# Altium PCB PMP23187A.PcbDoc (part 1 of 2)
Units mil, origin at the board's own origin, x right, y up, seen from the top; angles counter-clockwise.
Board outline 4000 x 3500 mil, 6 copper layers (Top Layer, Signal Layer 1, Signal Layer 2, Signal Layer 3, Signal Layer 4, Bottom Layer), stack 61.8 mil thick; 121 components, 42 nets, 273 pads, 535 vias.
Unrouted connection lines stored in the file: 23.
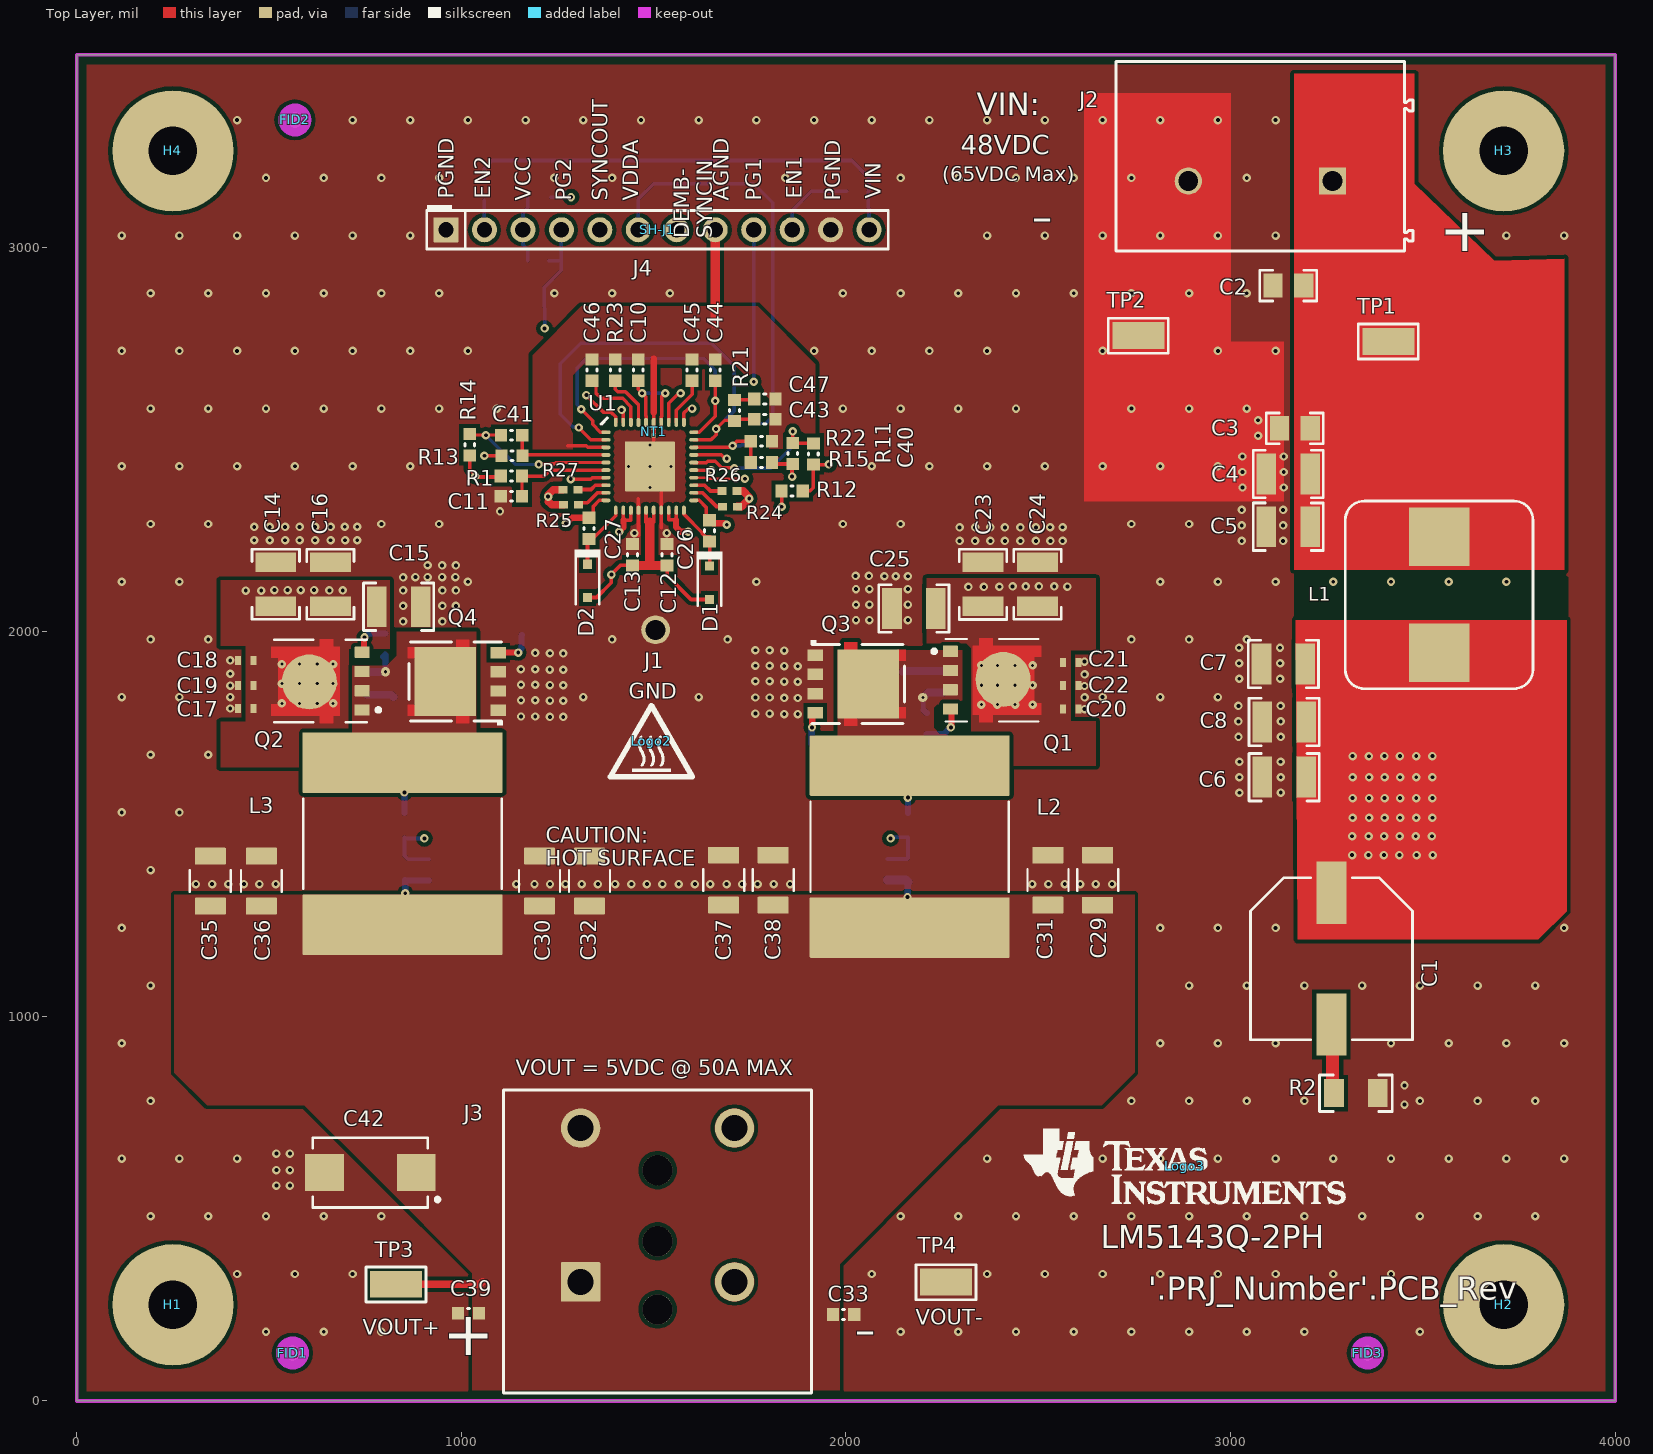
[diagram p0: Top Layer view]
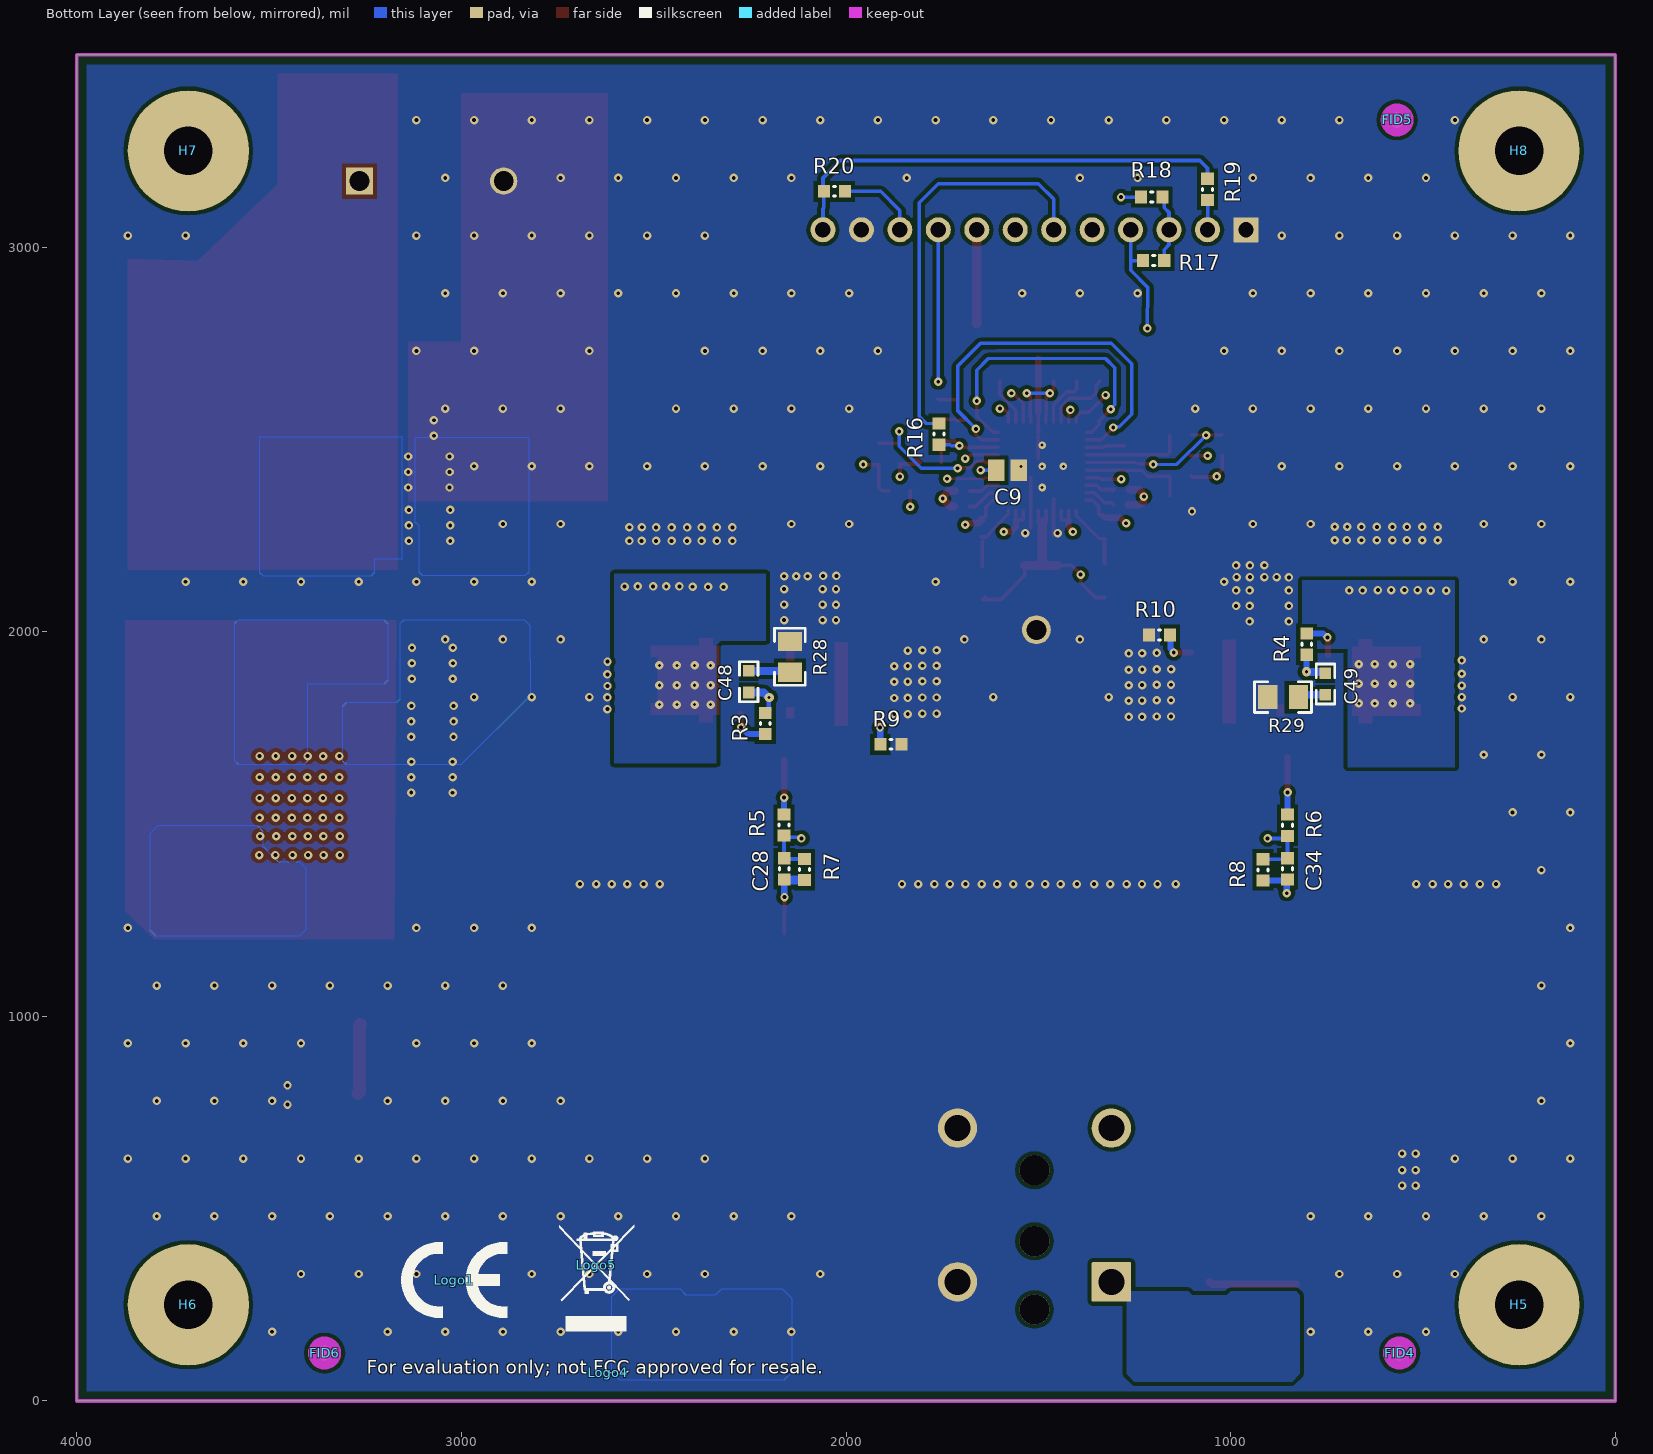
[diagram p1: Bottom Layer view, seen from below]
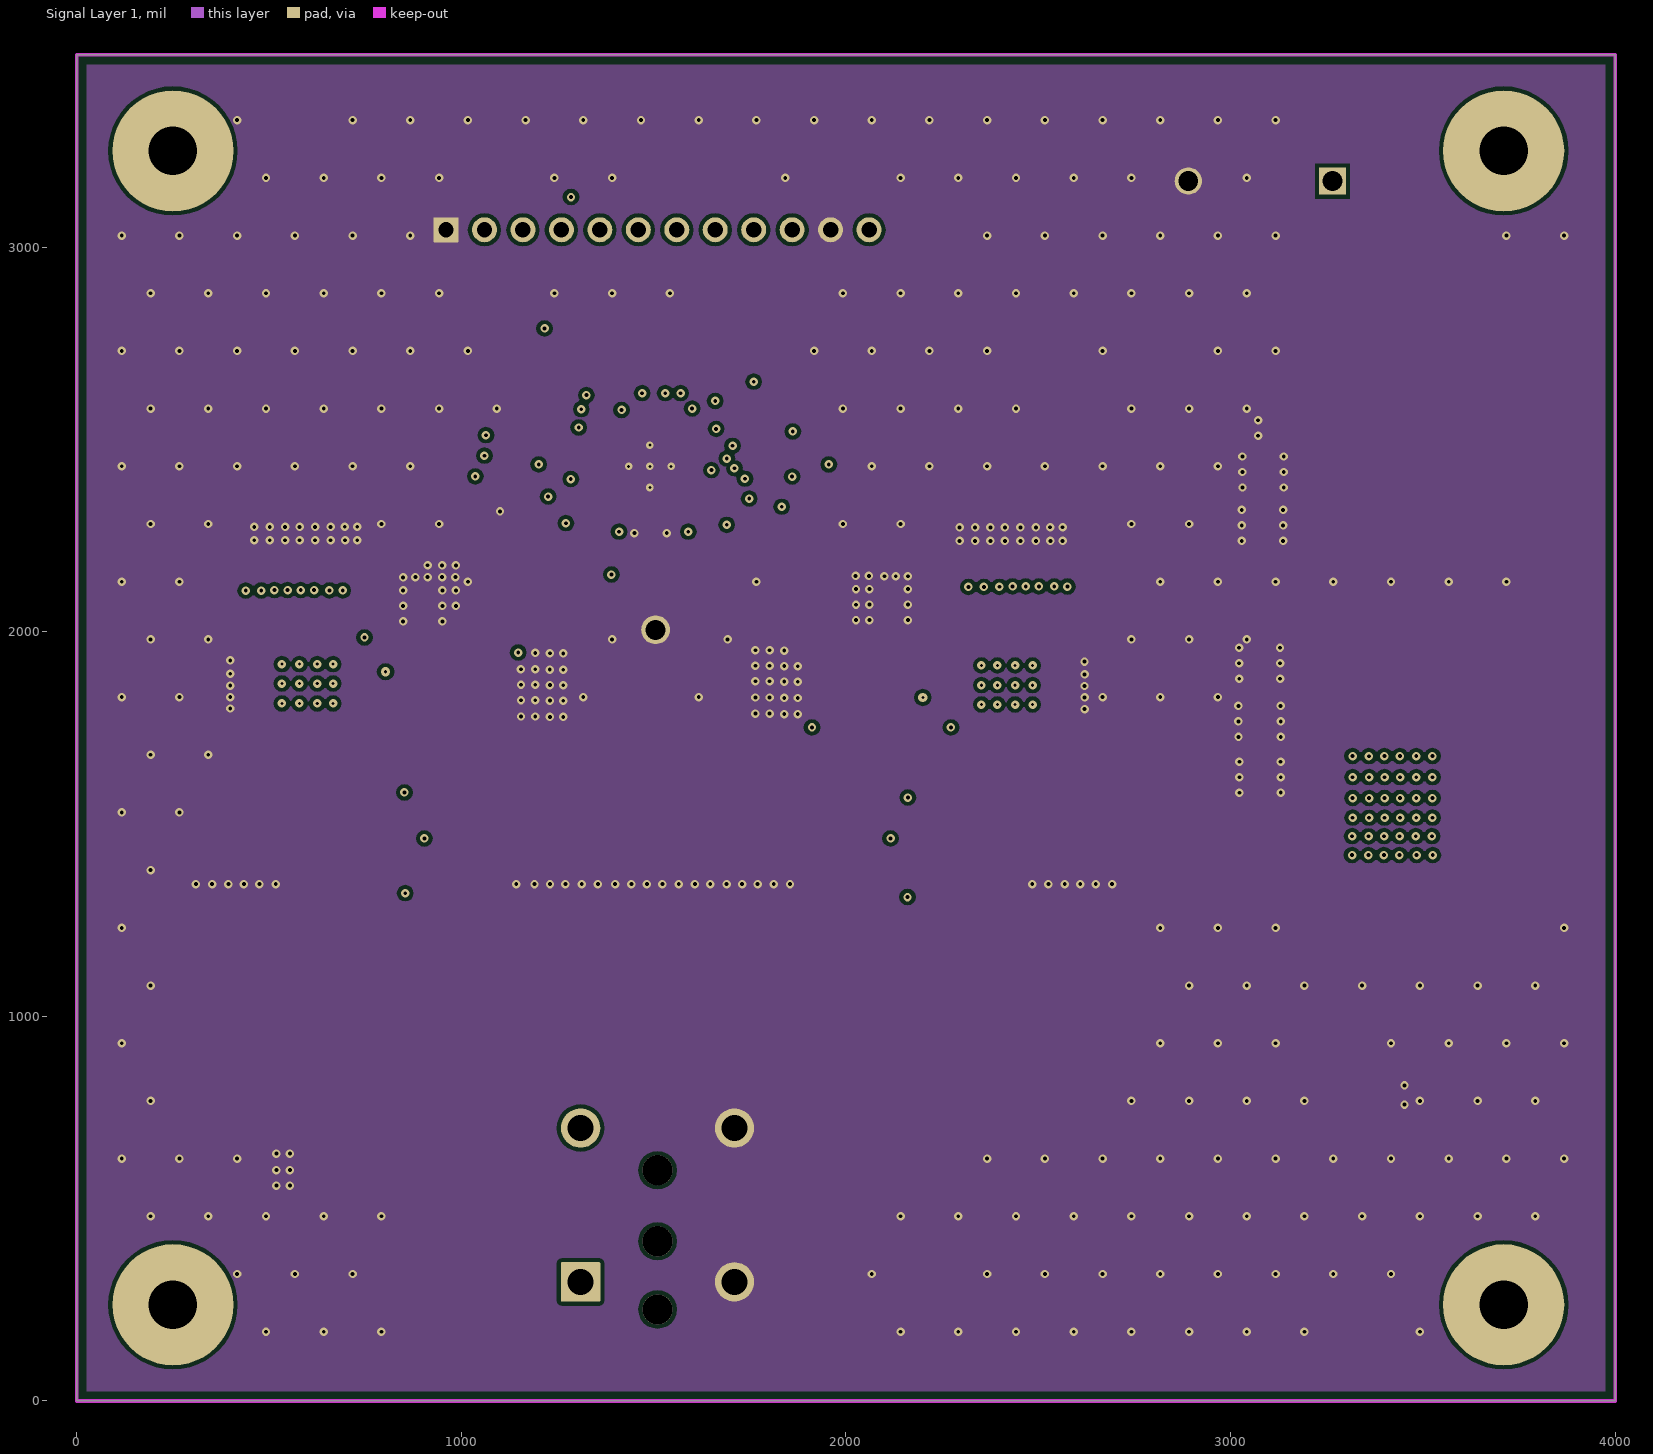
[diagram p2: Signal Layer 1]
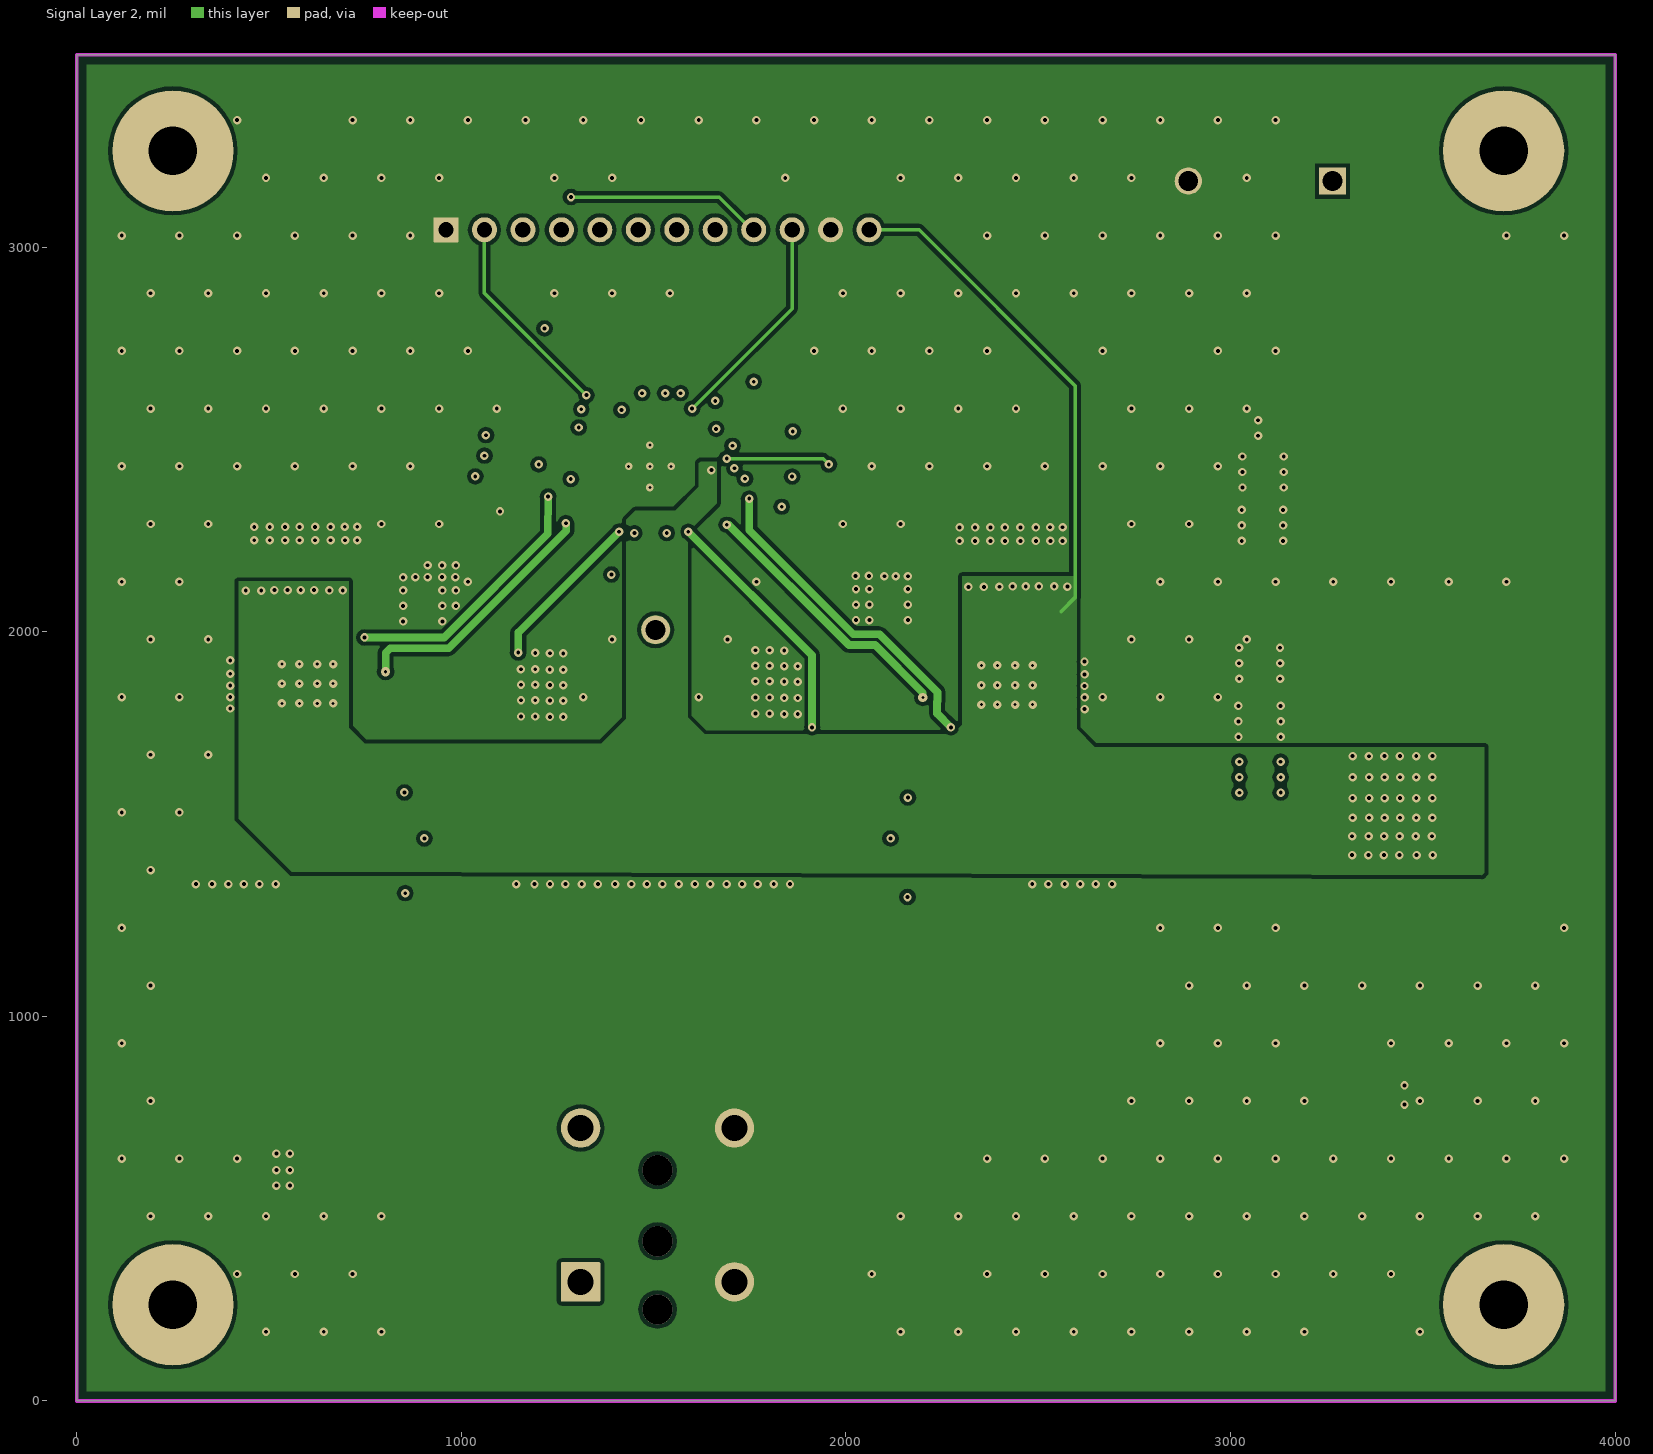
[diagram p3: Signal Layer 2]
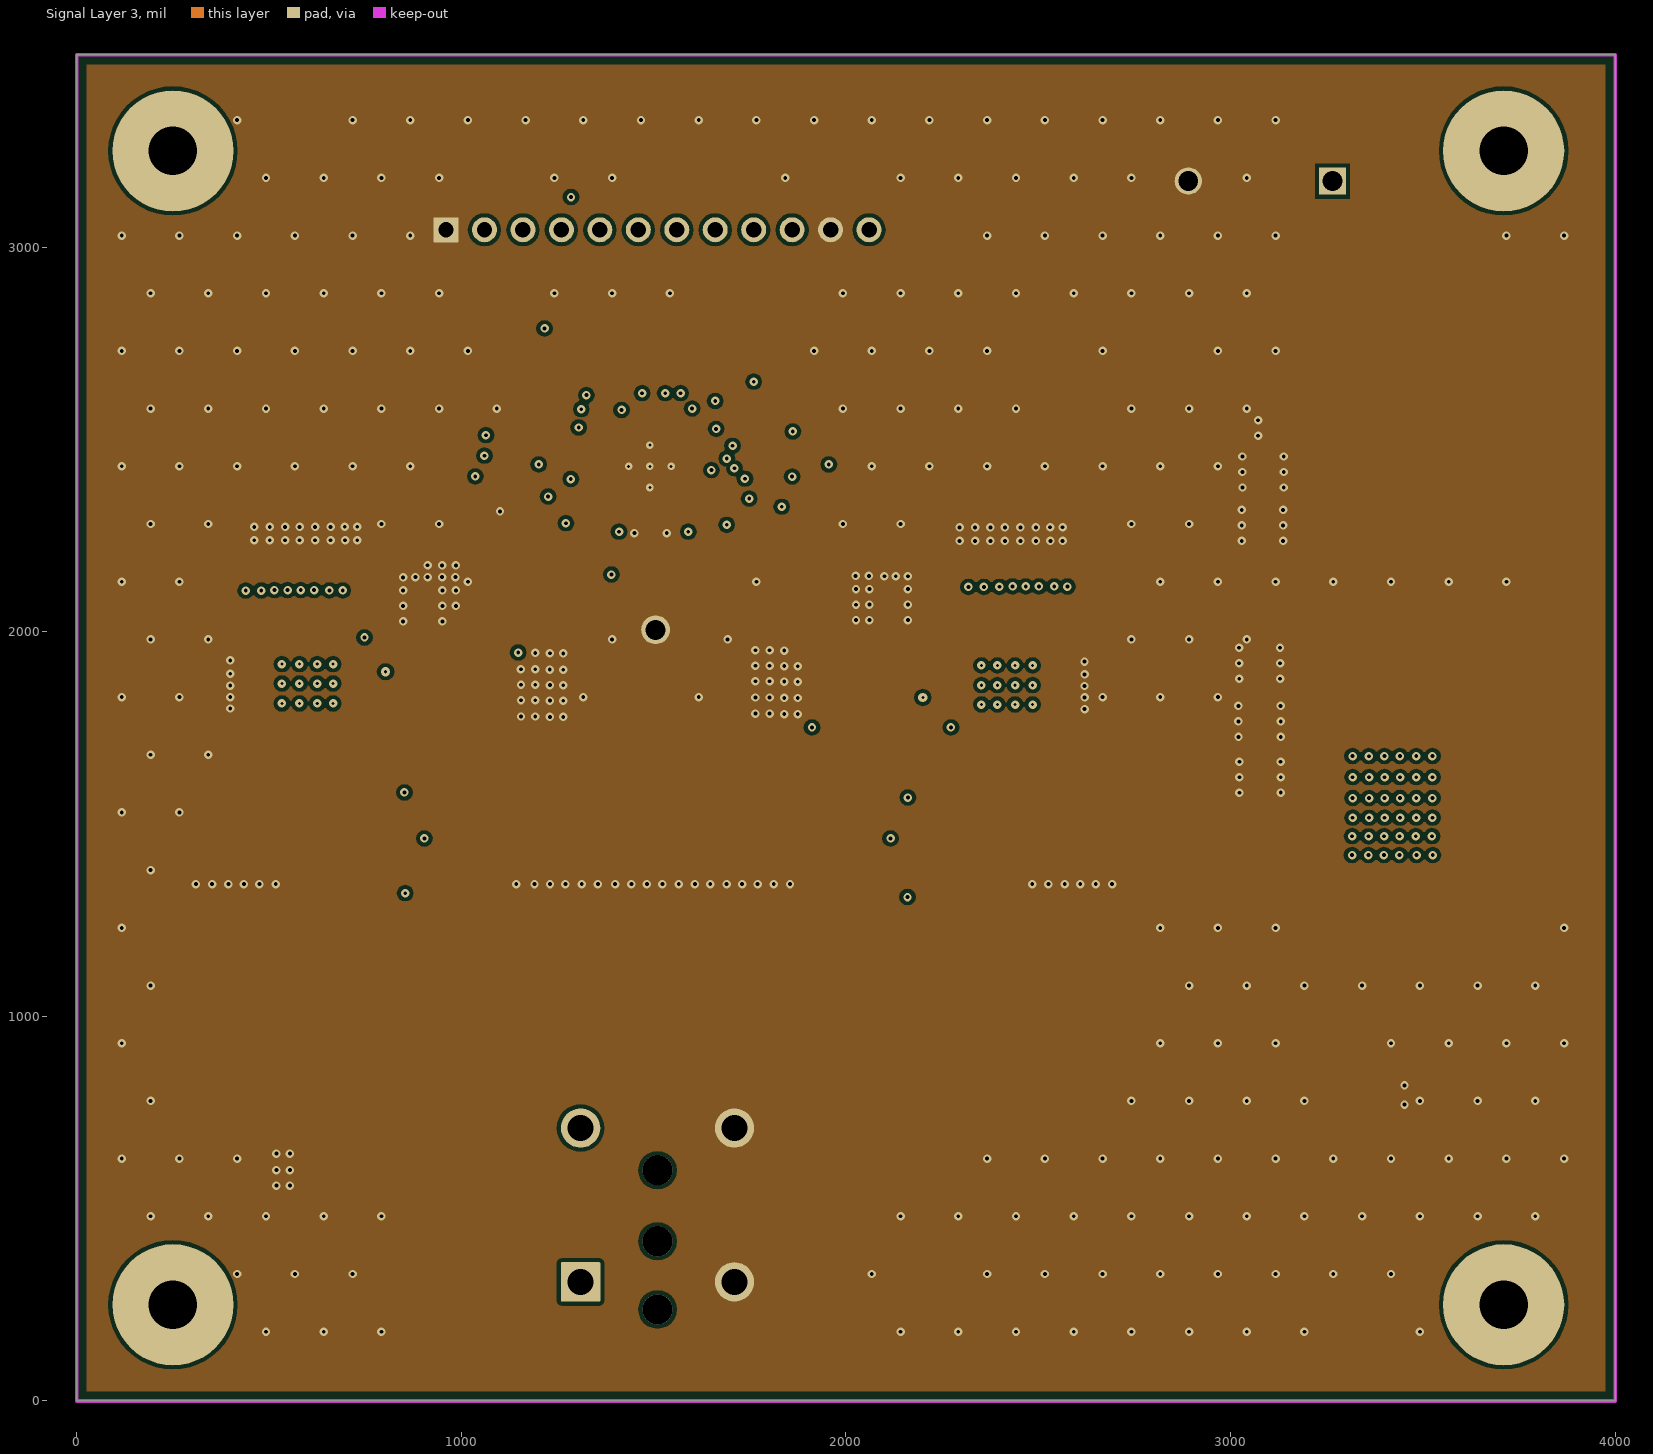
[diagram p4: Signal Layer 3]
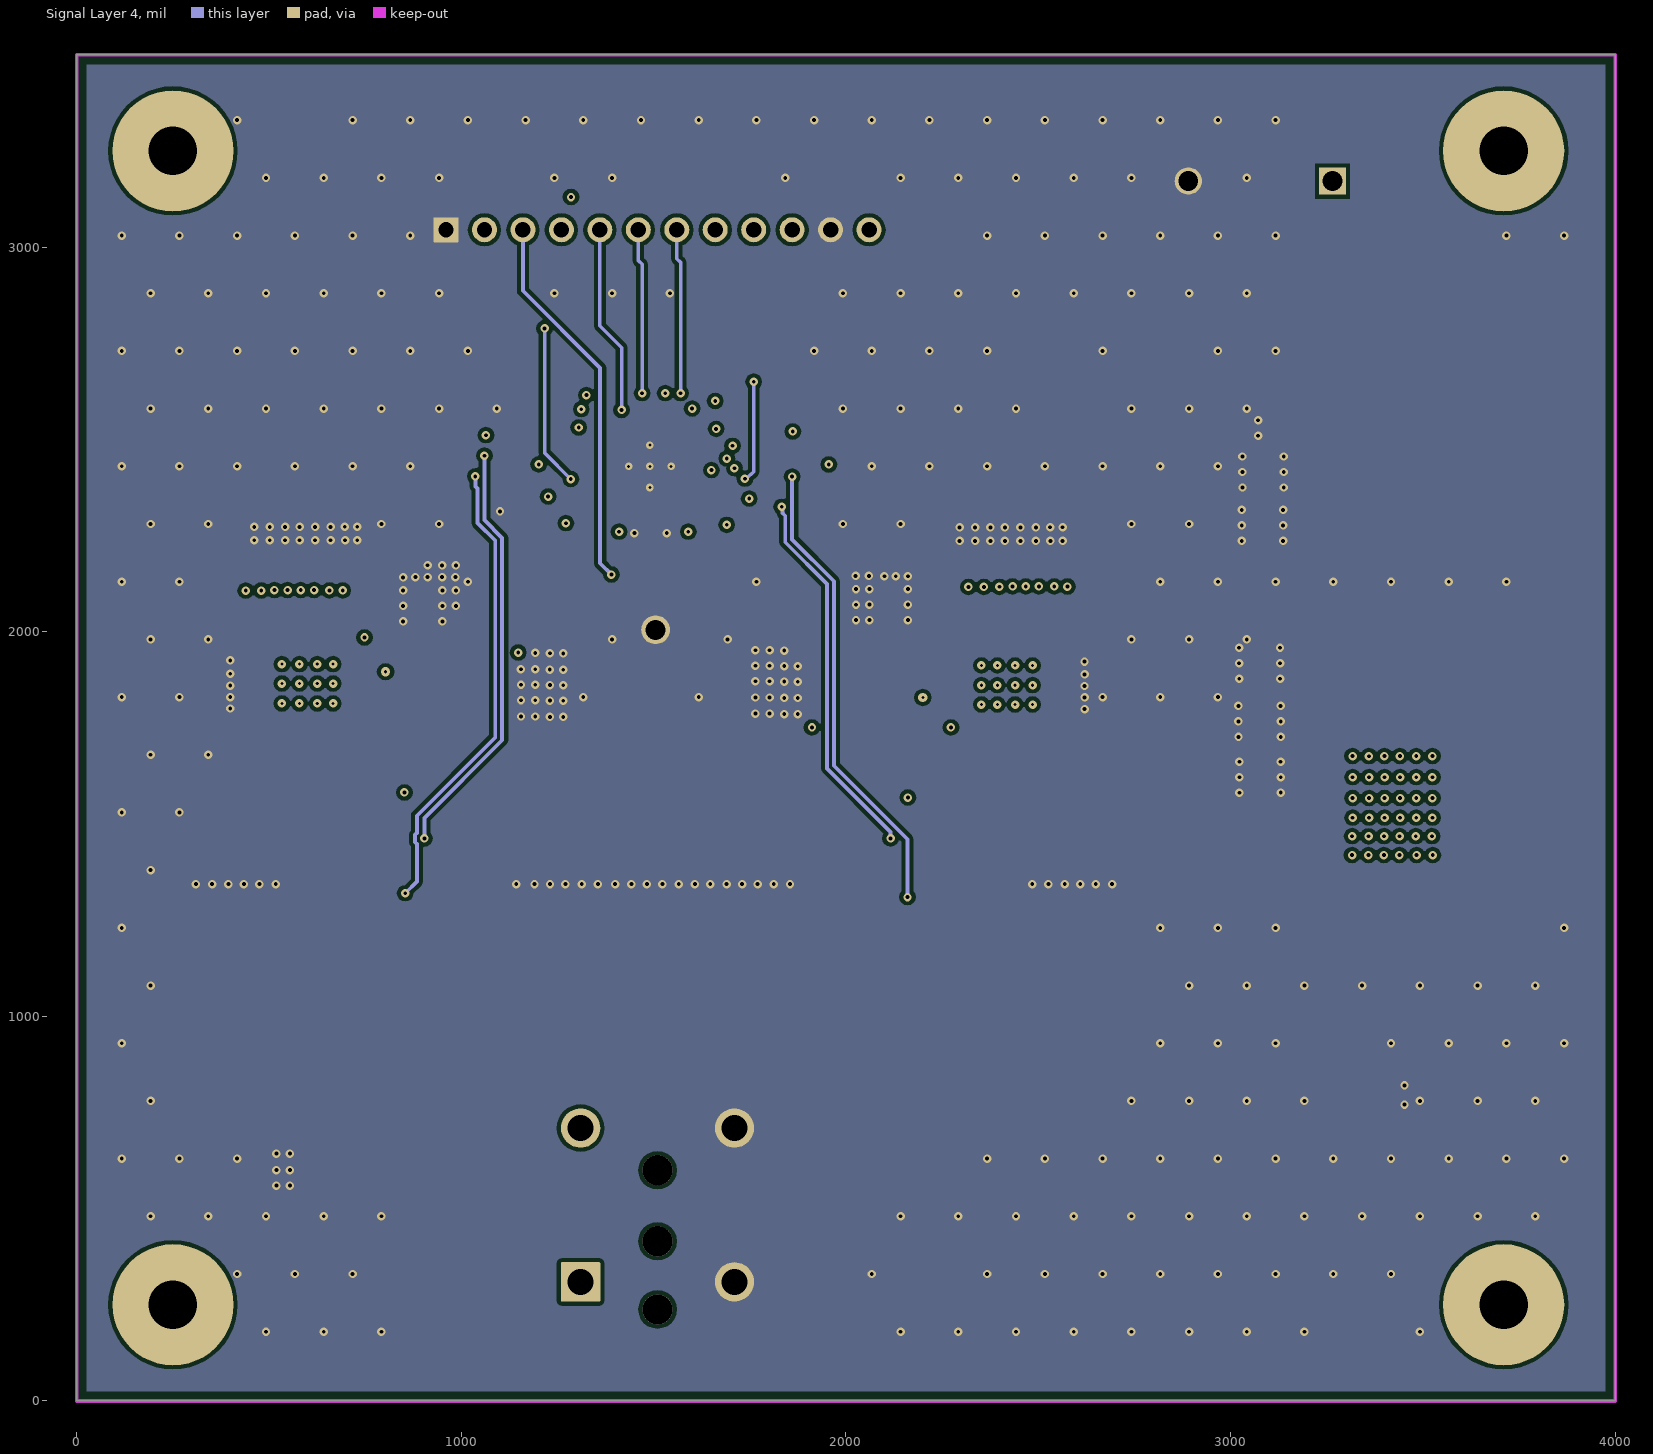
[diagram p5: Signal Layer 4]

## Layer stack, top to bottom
Top Solder: solder mask 0.4, Solder Resist, Dk 3.5
Top Layer: signal copper 2.8
Dielectric1: core 5, FR-4 High Tg, Dk 4.2
Signal Layer 1: signal copper 2.8
Dielectric 2: core 10, FR-4 High Tg, Dk 4.2
Signal Layer 2: signal copper 2.8
Dielectric 3: prepreg 15, FR-4 High Tg, Dk 4.2
Signal Layer 3: signal copper 2.8
Dielectric 4: core 10, FR-4 High Tg, Dk 4.2
Signal Layer 4: signal copper 2.8
Dielectric 5: prepreg 5, FR-4 High Tg, Dk 4.2
Bottom Layer: signal copper 2.8
Bottom Solder: solder mask 0.4, Solder Resist, Dk 3.5

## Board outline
0,0 0,3500 4000,3500 4000,0

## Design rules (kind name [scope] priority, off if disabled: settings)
AcuteAngle [All] p1: minimum=4.50000000000000E+0001 checktracksonly=FALSE
AssemblyTestPointUsage [All] p1: valid=2
BoardOutlineClearance BoardOutlineClearance_MountingHoles [OnCopper and InComponentClass('Mounting Holes')] p1: gap=40 ignorepadtopadclearanceinfootprint=FALSE
BoardOutlineClearance BoardOutlineClearance_Poly [OnCopper and IsPoly] p2: gap=25 ignorepadtopadclearanceinfootprint=FALSE
BoardOutlineClearance [OnCopper and Not InComponentClass('Logo') and not InComponentClass('FiducialMark') and not InRegion(1000,500,4000,800) and not InPoly] p3: gap=50 ignorepadtopadclearanceinfootprint=FALSE
Clearance "Clearance_EMI 2 Poly" [InNetClass('EMI-Clearance')] p1: gap=19.68 ignorepadtopadclearanceinfootprint=FALSE
Clearance Clearance_Keepouts [((IsTrack Or IsArc) And Not InPoly) And IsFree and IsKeepOut vs ((IsTrack Or IsArc) And Not InPoly) And IsFree and IsKeepOut] p2: gap=40 ignorepadtopadclearanceinfootprint=FALSE
Clearance Clearance_Poly [InPolygon] p3: gap=10 ignorepadtopadclearanceinfootprint=FALSE
Clearance Clearance_FiducialMark [IsKeepOut and InComponentClass('FiducialMark') vs IsPad and InComponentClass('FiducialMark')] p4: gap=0 ignorepadtopadclearanceinfootprint=FALSE
Clearance Clearance_MtgHole [HasFootprint('NY PMS 440 0025 PH') vs HasFootprint ('Keystone_1902C')] p5: gap=0 ignorepadtopadclearanceinfootprint=FALSE
Clearance [All] p6: gap=7.87 ignorepadtopadclearanceinfootprint=FALSE except(0: Arc-Hole Track-Hole SMDPad-Hole THPad-Hole Via-Hole Fill-Hole Poly-Hole Region-Hole Text-Hole)
ComponentClearance "ComponentClearance_Sheild H2" [InComponentClass('VOUT2') vs InComponent('H2')] p1: gap=20 collisioncheckmode=3 verticalgap=5 showdistances=FALSE
ComponentClearance "ComponentClearance_Shield H1" [InComponentClass('VOUT1') vs InComponent('H1')] p2: gap=20 collisioncheckmode=3 verticalgap=5 showdistances=FALSE
ComponentClearance ComponentClearance_NetTie [HasFootprint('Net-Tie_10mil') vs HasFootprint('RWG0040A')] p3: gap=0 collisioncheckmode=3 verticalgap=0 showdistances=FALSE
ComponentClearance ComponentClearance_MountingHoles_FiducialMarks [InComponentClass('Mounting Holes') vs InComponentClass('FiducialMark')] p4: gap=50 collisioncheckmode=3 verticalgap=10 showdistances=FALSE
ComponentClearance ComponentClearance_Shunt [InComponentClass('Header') vs InComponentClass('Shunt')] p5: gap=0 collisioncheckmode=3 verticalgap=0 showdistances=FALSE
ComponentClearance ComponentClearance_Logo [InComponentClass('Logo')] p6: gap=50 collisioncheckmode=3 verticalgap=10 showdistances=FALSE
ComponentClearance ComponentClearance_ScrewToNut [(HasFootprint('NY PMS 440 0025 PH')) vs (HasFootprint('Keystone_1902C'))] p7: gap=5 collisioncheckmode=3 verticalgap=10 showdistances=FALSE
ComponentClearance ComponentClearance_MountingHoles [InComponentClass('Mounting Holes')] p8: gap=100 collisioncheckmode=3 verticalgap=100000 showdistances=FALSE
ComponentClearance ComponentClearance_SmallPassives [HasFootprint('0201*') or HasFootprint('0402*') or HasFootprint('0508') or HasFootprint('0603*') or HasFootprint('0612') or HasFootprint('0805*') or HasFootprint('0815*') or HasFootprint('0830*') or HasFootprint('1206*') or HasFootprint('1210*') or HasFootprint('1808*') or HasFootprint('1812*') or HasFootprint('1825*') or HasFootprint('2010*') or HasFootprint('2220*') or HasFootprint('2225*') or HasFootprint('2512*') or HasFootprint('2728*') or HasFootprint('3518*') vs HasFootprint('0201*') or HasFootprint('0402*') or HasFootprint('0508') or HasFootprint('0603*') or HasFootprint('0612') or HasFootprint('0805*') or HasFootprint('0815*') or HasFootprint('0830*') or HasFootprint('1206*') or HasFootprint('1210*') or HasFootprint('1808*') or HasFootprint('1812*') or HasFootprint('1825*') or HasFootprint('2010*') or HasFootprint('2220*') or HasFootprint('2225*') or HasFootprint('2512*') or HasFootprint('2728*') or HasFootprint('3518*')] p9: gap=14.96 collisioncheckmode=3 verticalgap=10 showdistances=FALSE
ComponentClearance ComponentClearance_Shuint [HasFootprint('TSW-112-07-G-S') vs HasFootprint('Harwin_M7582-05')] p10: gap=0 collisioncheckmode=3 verticalgap=0 showdistances=FALSE
ComponentClearance ComponentClearance_THtoTH [IsThruComponent vs IsThruComponent] p11: gap=30 collisioncheckmode=3 verticalgap=30 showdistances=FALSE
ComponentClearance [All] p12: gap=30 collisioncheckmode=3 verticalgap=10 showdistances=FALSE
DiffPairsRouting [All] p1: maxlimit=100 minlimit=10 mostfreqgap=10 toplayer_minwidth=15 toplayer_maxwidth=15 toplayer_prefwidth=15 midlayer1_minwidth=15 midlayer1_maxwidth=15 midlayer1_prefwidth=15 midlayer2_minwidth=15 midlayer2_maxwidth=15 midlayer2_prefwidth=15 midlayer3_minwidth=15 midlayer3_maxwidth=15 midlayer3_prefwidth=15 midlayer4_minwidth=15 midlayer4_maxwidth=15 midlayer4_prefwidth=15 bottomlayer_minwidth=15 bottomlayer_maxwidth=15 bottomlayer_prefwidth=15 maxuncoupledlength=1000
FabricationTestPointUsage TestPointUsage [All] p1: valid=2 allowmultiple=FALSE
FabricationTestpoint Testpoint [All] p1: side=3 testpointundercomponent=TRUE minsize=40 maxsize=100 preferedsize=60 minholesize=0 maxholesize=40 preferedholesize=32 testpointgrid=1 allowsidetop=TRUE allowsidebottom=TRUE usegrid=TRUE gridtolerance=0.01
FanoutControl Fanout_LCC [IsLCC] p1: bgadir=Out bgaviamode=Centered fanoutstyle=Auto fanoutdirection=Alternating viagrid=1 // Fanout_LCC (Default Rule)
FanoutControl Fanout_BGA [IsBGA] p2: bgadir=Out bgaviamode=Centered fanoutstyle=Auto fanoutdirection=Alternating viagrid=1 // Fanout_BGA (Default Rule)
FanoutControl Fanout_Default [All] p4: bgadir=Out bgaviamode=Centered fanoutstyle=Auto fanoutdirection=Alternating viagrid=1 // Fanout_Default (Default Rule)
FanoutControl Fanout_Small [(CompPinCount < 5)] p5: bgadir=Out bgaviamode=Centered fanoutstyle=Auto fanoutdirection=OutThenIn viagrid=1 // Fanout_Small (Default Rule)
Height [All] p1: minheight=0 maxheight=2000 prefheight=500
HoleSize [All] p1: absolutevalues=TRUE maxlimit=251 minlimit=7.87 maxpercent=80.000 minpercent=20.000
MinimumAnnularRing MinimumAnnularRing_ThermalPadVias [IsVia and InAnyComponent] p1: minimumring=5.91
MinimumAnnularRing [All] p2: minimumring=6
MinimumSolderMaskSliver MinimumSolderMaskSliver_Logo [InComponentClass('Logo') vs InComponentClass('Logo')] p1: minsoldermaskwidth=0.7
MinimumSolderMaskSliver [All] p2: minsoldermaskwidth=3.94
PlaneClearance [All] p1: clearance=10
PlaneConnect [All] p1: planeconnectstyle=Relief reliefexpansion=10 reliefentries=4 reliefconductorwidth=10 reliefairgap=10
PolygonConnect [All] p1: connectstyle=Direct reliefconductorwidth=10 reliefentries=4 polygonreliefangle="90 Angle" airgapwidth=10
RoutingVias ThermalPadVias [IsVia and InAnyComponent] p1: holewidth=7.87 width=19.68 viastyle="Through Hole" minholewidth=7.87 minwidth=19.68 maxholewidth=12.99 maxwidth=23.62
RoutingVias [All] p2: holewidth=10 width=22 viastyle="Through Hole" minholewidth=7.87 minwidth=20 maxholewidth=40 maxwidth=65
SilkToBoardRegionClearance [Not ((IsComment or IsDesignator) And (Hide <> 'False')) and not InRegion(1000,500,4000,800)] p1:
SilkToSilkClearance SilkToSilkClearance_Pb-FreeLogo [(HasFootprint('Pb-Free_Overlay_Medium') OR HasFootprint('Pb-Free_Overlay_Small')) vs (HasFootprint('Pb-Free_Overlay_Medium') OR HasFootprint('Pb-Free_Overlay_Small'))] p1: silktosilkclearance=0
SilkToSilkClearance [All] p2: silktosilkclearance=4
SilkToSolderMaskClearance [IsPad] p1: minsilkscreentomaskgap=3.9 clearancetoexposedcopper=TRUE
SilkToSolderMaskClearance SilkToComponentPadClearance [(IsPad or IsFill or IsRegion) and InAnycomponent] p2: minsilkscreentomaskgap=3.9 clearancetoexposedcopper=TRUE
SolderMaskExpansion [All] p1: expansion=1.97 istentingtop=FALSE
Width [All] p1: maxlimit=100 minlimit=6 preferedwidth=10 checkconnectedcopper=TRUE
13 further rules are at their usual default settings.

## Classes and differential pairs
component class "Mounting Holes": H1 H2 H3 H4
component class Logo: Logo3
component class PMP23187A-HW: FID1 FID2 FID3 FID4 FID5 FID6 H1 H2 H3 H4 H5 H6 H7 H8 Logo1 Logo2 Logo3 Logo4 Logo5 SH-J1 ZZ1 ZZ2 ZZ3 ZZ4
component class FiducialMark: FID1 FID2 FID3 FID4 FID5 FID6
component class AssemblyNote: ZZ1 ZZ2 ZZ3 ZZ4
component class Header: J4
component class PMP23187A-SCH: C1 C2 C3 C4 C5 C6 C7 C8 C9 C10 C11 C12 C13 C14 C15 C16 C17 C18 C19 C20 C21 C22 C23 C24 C25 C26 C27 C28 C29 C30 C31 C32 C33 C34 C35 C36 C37 C38 C39 C40 C41 C42 C43 C44 C45 C46 C47 C48 C49 D1 D2 J1 J2 J3 J4 L1 L2 L3 NT1 Q1 Q2 Q3 Q4 R1 R2 R3 R4 R5 R6 R7 R8 R9 R10 R11 R12 R13 R14 R15 R16 R17 R18 R19 R20 R21 R22 R23 R24 R25 R26 R27 R28 R29 TP1 TP2 TP3 TP4 U1

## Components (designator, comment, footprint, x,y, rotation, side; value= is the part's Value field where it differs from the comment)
C1 "EEE-FC1H470P" SM_RADIAL_G 3262.25,1150 r270 top value=47uF
C2 "C0805C104K1RACTU" 0805_HV 3149.91,2900 r0 top value=0.1uF
C3 "C0805C104K1RACTU" 0805_HV 3166.76,2528.71 r180 top value=0.1uF
C4 "GCM32DC72A475KE02L" 1210_220 3149.91,2410 r180 top value=4.7uF
C5 "GCM32DC72A475KE02L" 1210_220 3149.91,2272.71 r180 top value=4.7uF
C6 "GCM32DC72A475KE02L" 1210_220 3139.23,1621.73 r180 top value=4.7uF
C7 "GCM32DC72A475KE02L" 1210_220 3137.27,1915.89 r180 top value=4.7uF
C8 "GCM32DC72A475KE02L" 1210_220 3139.23,1765.42 r180 top value=4.7uF
C9 "GRM21BR72A474KA73L" 0805L 1580,2420 r0 bottom value=0.47uF
C10 "GCM188R71C474KA55D" 0603L 1460,2680 r270 top value=0.47uF
C11 "GRM188R71A225KE15D" 0603L 1130,2351.98 r180 top value=2.2uF
C12 "GRM188R71A225KE15D" 0603L 1535,2200 r90 top value=2.2uF
C13 "GRM188R71A225KE15D" 0603L 1445,2200 r90 top value=2.2uF
C14 "GCM32DC72A475KE02L" 1210_220 517.43,2123.15 r90 top value=4.7uF
C15 "GCM32DC72A475KE02L" 1210_220 836.92,2065 r0 top value=4.7uF
C16 "GCM32DC72A475KE02L" 1210_220 659.3,2123.15 r90 top value=4.7uF
C17 "CGA2B3X7S2A103K050BB" 0402S 439.32,1800.28 r180 top value=0.01uF
C18 "CGA2B3X7S2A103K050BB" 0402S 439.32,1924.77 r180 top value=0.01uF
C19 "CGA2B3X7S2A103K050BB" 0402S 439.32,1859.77 r180 top value=0.01uF
C20 "CGA2B3X7S2A103K050BB" 0402S 2584.45,1798.94 r0 top value=0.01uF
C21 "CGA2B3X7S2A103K050BB" 0402S 2584.45,1920 r0 top value=0.01uF
C22 "CGA2B3X7S2A103K050BB" 0402S 2584.45,1860 r0 top value=0.01uF
C23 "GCM32DC72A475KE02L" 1210_220 2356.37,2123.15 r90 top value=4.7uF
C24 "GCM32DC72A475KE02L" 1210_220 2497.89,2123.15 r90 top value=4.7uF
C25 "GCM32DC72A475KE02L" 1210_220 2176.58,2060 r180 top value=4.7uF
C26 "CGA3E2X7R1E104K080AA" 0603L 1645.22,2262.27 r270 top value=0.1uF
C27 "CGA3E2X7R1E104K080AA" 0603L 1331.69,2268.58 r270 top value=0.1uF
C28 "CGA3E2X7R1E104K080AA" 0603L 2160.55,1383.47 r270 bottom value=0.1uF
C29 "GRM32EE70J107ME15L" FP-GRM32EE70J107ME15L_1210-MFG 2654.39,1354.15 r270 top value=100µF
C30 "GRM32EE70J107ME15L" FP-GRM32EE70J107ME15L_1210-MFG 1203.13,1351.69 r270 top value=100µF
C31 "GRM32EE70J107ME15L" FP-GRM32EE70J107ME15L_1210-MFG 2525.08,1354.16 r270 top value=100µF
C32 "GRM32EE70J107ME15L" FP-GRM32EE70J107ME15L_1210-MFG 1332.97,1351.69 r270 top value=100µF
C33 "GRM188R72A104KA35D" 0603L 1993.77,224.91 r0 top value=0.1uF
C34 "CGA3E2X7R1E104K080AA" 0603L 851.99,1383.47 r270 bottom value=0.1uF
C35 "GRM32EE70J107ME15L" FP-GRM32EE70J107ME15L_1210-MFG 347.2,1351.69 r270 top value=100µF
C36 "GRM32EE70J107ME15L" FP-GRM32EE70J107ME15L_1210-MFG 480,1351.69 r270 top value=100µF
C37 "GRM32EE70J107ME15L" FP-GRM32EE70J107ME15L_1210-MFG 1682.02,1354.16 r270 top value=100µF
C38 "GRM32EE70J107ME15L" FP-GRM32EE70J107ME15L_1210-MFG 1810.72,1354.16 r270 top value=100µF
C39 "CGA3E2X7R1E104K080AA" 0603L 1018.32,228.09 r180 top value=0.1uF
C40 "06031A330JAT2A" 0603L 1915.04,2462.09 r270 top value=33pF
C41 "06031A330JAT2A" 0603L 1130.67,2510.9 r0 top value=33pF
C42 "T598D227M010ATE025" 7343-31 763.24,593.5 r180 top value=220uF
C43 "06035A151JAT2A" 0603L 1788.89,2552.19 r0 top value=150pF
C44 "CGA3E2X7R1E104K080AA" 0603L 1660,2680 r90 top value=0.1uF
C45 "CL10B224KO8VPNC" 0603L 1600,2680 r90 top value=0.22uF
C46 "GRM188R72A103KA01D" 0603L 1340,2680 r90 top value=0.01uF
C47 "GRM1885C1H682JA01D" 0603L 1788.89,2605.32 r0 top value=6800pF
C48 "06031C221KAT2A" 0603_HV 2252.93,1869.94 r90 bottom value=220pF
C49 "06031C221KAT2A" 0603_HV 753.64,1863.95 r270 bottom value=220pF
D1 "60V" SOD-323F 1645.22,2127.18 r270 top
D2 "60V" SOD-323F 1327.71,2132.07 r270 top
FID1 "Fiducial" Fiducial10-20 560.66,124.51 r0 top
FID2 "Fiducial" Fiducial10-20 567,3330.46 r0 top
FID3 "Fiducial" Fiducial10-20 3355.63,124.51 r0 top
FID4 "Fiducial" Fiducial10-20 560.66,124.51 r180 bottom
FID5 "Fiducial" Fiducial10-20 567,3330.46 r180 bottom
FID6 "Fiducial" Fiducial10-20 3355.63,124.51 r180 bottom
H1 "NY PMS 440 0025 PH" "NY PMS 440 0025 PH" 250,250 r0 top
H2 "NY PMS 440 0025 PH" "NY PMS 440 0025 PH" 3710,250 r0 top
H3 "NY PMS 440 0025 PH" "NY PMS 440 0025 PH" 3710,3250 r0 top
H4 "NY PMS 440 0025 PH" "NY PMS 440 0025 PH" 250,3250 r0 top
H5 "1902C" Keystone_1902C 250,250 r180 bottom
H6 "1902C" Keystone_1902C 3710,250 r180 bottom
H7 "1902C" Keystone_1902C 3710,3250 r180 bottom
H8 "1902C" Keystone_1902C 250,3250 r180 bottom
J1 "1040" CONN_1040 1505,2005 r270 top
J2 "1714971" Phoenix_1714971 3077.46,3171.73 r180 top
J3 "EM292902-UL" Eaton_EM292902 1510,414.96 r0 top
J4 "TSW-112-07-G-S" TSW-112-07-G-S 1510,3045 r0 top
L1 "744325420" WE-HC6 3542.16,2095.94 r270 top value=4.2uH
L2 "VCUD128T-1R5M58" FP-VCUD128T-1R5M58_SMD2-MFG 2165.55,1441.31 r90 top value=1.5uH
L3 "VCUD128T-1R5M58" FP-VCUD128T-1R5M58_SMD2-MFG 846.99,1449.11 r270 top value=1.5uH
Logo1 "CE Mark" CE_Mark_5mm 3018.31,314.23 r180 bottom
Logo2 "CAUTION HOT SURFACE" IEC_HotSurface_Small 1494.02,1715.48 r0 top
Logo3 "Texas Instruments" TI_Stacked_Overlay_Small 2880.51,610 r0 top
Logo4 "FCC disclaimer" FCC_disclaimer 2618.61,73 r180 bottom
Logo5 "WEEE logo" WEEE_Minimum 2650,352.99 r180 bottom
NT1 "Net-Tie" Net-Tie_10mil 1499.84,2520 r270 top net-tie
Q1 "NVMFS6H852NLWFT1G" FP-NVMFS6H852NLWFT1G_DFN5-MFG 2379.7,1874 r270 top
Q2 "NVMFS6H852NLWFT1G" FP-NVMFS6H852NLWFT1G_DFN5-MFG 633.56,1871.5 r90 top
Q3 "NVMFS6H801NT1G" SO-8FL 2030,1863.94 r0 top value=80V
Q4 "NVMFS6H801NT1G" SO-8FL 985.79,1870.63 r180 top value=80V
R1 "RC0603FR-071RL" 0603L 1130,2404.43 r180 top value=1.00
R2 "CRCW12061R00JNEA" 1206 3325.71,800 r180 top value=1.0
R3 "CRCW0603100KFKEA" 0603L 2210,1761.39 r90 bottom value=100k
R4 "CRCW0603100KFKEA" 0603L 801.97,1967.48 r90 bottom value=100k
R5 "RC0603FR-074K87L" 0603L 2161.05,1497.2 r90 bottom value=4.87k
R6 "RC0603FR-074K87L" 0603L 851.99,1496.81 r90 bottom value=4.87k
R7 "CRCW0603100KFKEA" 0603L 2107.69,1381.66 r270 bottom value=100k
R8 "CRCW0603100KFKEA" 0603L 915.95,1380.67 r90 bottom value=100k
R9 "CRCW0603100KFKEA" 0603L 1883.06,1707.2 r180 bottom value=100k
R10 "CRCW0603100KFKEA" 0603L 1185.07,1991.64 r180 bottom value=100k
R11 "CRCW06030000Z0EA" 0603L 1861.65,2463.44 r270 top value=0
R12 "CRCW0603100RFKEA" 0603L 1860,2366.1 r180 top value=100
R13 "CRCW0603100RFKEA" 0603L 1131.67,2457.56 r180 top value=100
R14 "CRCW06030000Z0EA" 0603L 1021.61,2486.14 r270 top value=0
R15 "CRCW0603100KFKEA" 0603L 1780,2440 r0 top value=100k
R16 "CRCW06030000Z0EA" 0603L 1758.35,2513.7 r90 bottom value=0
R17 "CRCW0603100KFKEA" 0603L 1200,2965 r180 bottom value=100k
R18 "CRCW0603100KFKEA" 0603L 1205,3130 r180 bottom value=100k
R19 "CRCW0603100KFKEA" 0603L 1060,3150 r90 bottom value=100k
R20 "CRCW0603100KFKEA" 0603L 2030,3145 r0 bottom value=100k
R21 "RC0603FR-074K99L" 0603L 1710,2575 r270 top value=4.99k
R22 "CRCW060322K1FKEA" 0603L 1780,2495 r180 top value=22.1k
R23 "RC0603FR-0773K2L" 0603L 1400,2680 r270 top value=73.2k
R24 "ERJ-2GE0R00X" 0402L 1698.43,2325.25 r180 top value=0
R25 "ERJ-2GE0R00X" 0402L 1285,2330.16 r180 top value=0
R26 "ERJ-2GE0R00X" 0402L 1697.11,2365.74 r180 top value=0
R27 "ERJ-2GE0R00X" 0402L 1283.59,2369.38 r180 top value=0
R28 "ERJ-6GEYJ2R2V" 0805_HV 2145.66,1934.6 r270 bottom value=2.2
R29 "ERJ-6GEYJ2R2V" 0805_HV 863.74,1830 r180 bottom value=2.2
SH-J1 "M7582-05" Harwin_M7582-05 1510.85,3045 r180 top
TP1 "5015" Testpoint_Keystone_Miniature 3410,2755 r0 top
TP2 "5015" Testpoint_Keystone_Miniature 2760,2770 r0 top
TP3 "5015" Testpoint_Keystone_Miniature 830,303.42 r0 top
TP4 "5015" Testpoint_Keystone_Miniature 2260,309.45 r0 top
U1 "LM5143QRWGRQ1" RWG0040A 1490,2430 r0 top
ZZ1 "These assemblies are ESD sensitive, ESD precautions shall be observed." AssemblyNote 248.78,4344.11 r0 top
ZZ2 "These assemblies must be clean and free from flux and all contaminants. Use of no clean flux is not acceptable." AssemblyNote 248.78,4258.43 r0 top
ZZ3 "These assemblies must comply with workmanship standards IPC-A-610 Class 2, unless otherwise specified." AssemblyNote 248.78,4172.74 r0 top
ZZ4 "Place Shunt Jumper SH-J1 onto J2 onto pins 6-7 (VDDA - DEMB-SYNCIN)" AssemblyNote 250,4080 r0 top

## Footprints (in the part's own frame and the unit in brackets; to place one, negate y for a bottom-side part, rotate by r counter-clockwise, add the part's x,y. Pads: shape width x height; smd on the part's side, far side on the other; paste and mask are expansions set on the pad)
0402L [mm] "0402 from SM-752 data"
  rect 0.6x0.5 smd: 1(-0.5,0) 2(0.5,0)
  body extent -0.55,-0.3 0.55,0.3, height 0.6
0402S [mil] "Based on C0402S footprint from PADS legacy"
  rect 15x24 smd: 1(-20,0) 2(20,0)
  body extent -22,-12 22,12, height 24
0603_HV [mil] "Ernesto recommended land pattern.  26 mil between pads."
  rect 30x30 smd: 1(-28,0) 2(28,0)
  silkscreen extent -52,-24 52,24, body extent -34,-19 34,19, height 39
0603L [mm] "0603 from SM-752 data"
  rect 0.8x0.85 smd: 1(-0.7,0) 2(0.7,0)
  silkscreen extent -0.07,-0.33 0.07,0.33, body extent -0.87,-0.47 0.87,0.47, height 1
0805_HV [mil] "0805 with 30mil clearance between pads"
  rect 50x63 smd: 1(-40,0) 2(40,0)
  silkscreen extent -74,-40 74,40, body extent -43,-29 43,29, height 57
0805L [mm] "0805 from SM-752 data"
  rect 1.1x1.4 smd: 1(-0.75,0) 2(0.75,0)
  body extent -1.1,-0.72 1.1,0.72, height 1.45
1206 [mm] "1206 from SM-752 data"
  rect 1.3x1.85 smd: 1(-1.45,0) 2(1.45,0)
  silkscreen extent -2.4,-1.21 2.4,1.21, body extent -1.7,-0.9 1.7,0.9, height 1.35
1210_220 [mm] "1210"
  rect 1.3x2.7 smd: 1(-1.45,0) 2(1.45,0)
  silkscreen extent -2.32,-1.57 2.32,1.57, body extent -1.7,-1.35 1.7,1.35, height 2.2
7343-31 [mm] "Medium Density based on Kemet T495 dimensions"
  rect 2.55x2.45 smd: 1(-3.025,0) 2(3.025,0)
  silkscreen extent -4.56,-2.3 3.8,2.3, body extent -3.8,-2.3 3.8,2.3, height 3.1
AssemblyNote [mil] "Assembly Note"
CE_Mark_5mm [mil] "Minimum text height for CE Mark"
  silkscreen extent -138,-98 138,98
CONN_1040 [mil] "Test Point, PC  test point Terminal"
  round 75 hole 52: 1(0,0)
  body extent -55,-12 55,13, height 276
Eaton_EM292902 [mm] "Terminal Block, 10.16mm, 2x1, TH"
  rrect4% 2.6x2.6 hole 1.7 paste-1000 mask+0: 1(-5.08,-2.68)
  round 2.6 hole 1.7 paste-1000 mask+0: 1(-5.08,7.48) 2(5.08,-2.68) 2(5.08,7.48)
  round 2 hole 2 unplated paste-1000 mask+0: ""(0,-4.5) ""(0,0) ""(0,4.7)
  silkscreen extent -10.17,-10.02 10.17,9.98, body extent -10.27,-10.12 10.27,10.08, height 0.25
FCC_disclaimer [mil]
Fiducial10-20 [mm]
  round 1 smd mask+0.5: 1(0,0)
  Top Layer keep-out circle w1.178: c0,0 r0.5
FP-GRM32EE70J107ME15L_1210-MFG [mm]
  rrect9% 1.1x2.05 smd paste+0 mask+0: 1(-1.65,0) 2(1.65,0)
  silkscreen extent -0.72,-1.35 0.72,1.35, body extent -2.3,-1.45 2.3,1.45, height 0.25
FP-NVMFS6H852NLWFT1G_DFN5-MFG [mm]
  rrect13% 0.75x1 smd paste+0 mask+0: 1(-1.905,-2.748) 2(-0.635,-2.748) 3(0.635,-2.748) 4(1.905,-2.748)
  round 3.631 smd paste+0 mask+0: 5-6(-0.05,0.735)
  Top Layer region: -2.28,-1.282 -2.28,-0.857 -2.775,-0.857 -2.775,0.048 -2.28,0.048 -2.28,3.247 -1.53,3.247 -1.53,2.772 1.53,2.772 1.53,3.247 2.28,3.247 2.28,0.048 2.775,0.048 2.775,-0.857 2.28,-0.857 2.28,-1.282
  silkscreen extent -2.73,-3.95 2.73,3.05, body extent -2.88,-3.35 2.88,3.35, height 0.25
FP-VCUD128T-1R5M58_SMD2-MFG [mm]
  rrect3% 4x13.2 smd paste+0 mask+0: 1(-5.35,0) 2(5.35,0)
  silkscreen extent -2.98,-6.55 2.98,6.55, body extent -7.45,-6.7 7.45,6.7, height 0.25
Harwin_M7582-05 [mil] "Single Operation 2.54mm Pitch Open Top Jumper Socket"
  body extent -98,-47 98,47, height 236
IEC_HotSurface_Small [mil]
  silkscreen extent -107,-93 107,92
Keystone_1902C [mil] "Hex Standoff, 4-40 threaded, nylon"
  round 1 on Mech4: 0(0,0)
  body extent -145,-126 146,126, height 501
Net-Tie_10mil [mil] "10mil net tie, no solder mask opening, no solder paste"
  rect 10x10 smd paste-5 mask-5: 1(-10,0) 2(10,0)
  Top Layer region: -6,5 6,5 6,-5 -6,-5
"NY PMS 440 0025 PH" [mm] "4-40 nylon screw and mounting hole"
  round 8 hole 3.2: 1(0,0)
  body extent -3.3,-3.3 3.3,3.3, height 2.69
Phoenix_1714971 [mm] "Receptacle, 9.52mm, 2x1, TH"
  rect 1.8x1.8 hole 1.3: 1(-4.76,0)
  round 1.8 hole 1.3: 2(4.76,0)
  silkscreen extent -10.08,-7.89 9.53,4.61, body extent -10.09,-7.9 9.52,4.6, height 22
RWG0040A [mm] "QFN, 40-Leads, Body 6x6mm, Pitch 0.5mm, Thermal Pad 3.3 x 3.3mm, TI Recommended"
  rrect7% 1.43x1.43 on Top Paste: 0(-0.815,-0.815) 0(-0.815,0.815) 0(0.815,-0.815) 0(0.815,0.815)
  rrect100% 0.6x0.25 smd: 1(-2.9,2.25) 2(-2.9,1.75) 3(-2.9,1.25) 4(-2.9,0.75) 5(-2.9,0.25) 6(-2.9,-0.25) 7(-2.9,-0.75) 8(-2.9,-1.25) 9(-2.9,-1.75) 10(-2.9,-2.25) 21(2.9,-2.25) 22(2.9,-1.75) 23(2.9,-1.25) 24(2.9,-0.75) 25(2.9,-0.25) 26(2.9,0.25) 27(2.9,0.75) 28(2.9,1.25) 29(2.9,1.75) 30(2.9,2.25)
  rrect100% 0.25x0.6 smd: 11(-2.25,-2.9) 12(-1.75,-2.9) 13(-1.25,-2.9) 14(-0.75,-2.9) 15(-0.25,-2.9) 16(0.25,-2.9) 17(0.75,-2.9) 18(1.25,-2.9) 19(1.75,-2.9) 20(2.25,-2.9) 31(2.25,2.9) 32(1.75,2.9) 33(1.25,2.9) 34(0.75,2.9) 35(0.25,2.9) 36(-0.25,2.9) 37(-0.75,2.9) 38(-1.25,2.9) 39(-1.75,2.9) 40(-2.25,2.9)
  rrect3% 3.3x3.3 smd paste-1.65: 41(0,0)
  silkscreen extent -3.21,2.78 -2.79,3.2, body extent -3,-3 3,3, height 0.86
SM_RADIAL_G [mm] "10 x 10.2mm:  Panasonic G"
  rect 4.1x2 smd: 1(-4.35,0) 2(4.35,0)
  silkscreen extent -5.35,-5.35 5.35,5.35, body extent -5.25,-5.25 5.25,5.25, height 10.5
SO-8FL [mm] "ON SEMICONDUCTOR, DFN5 5x6, 1.27P, CASE 488AA"
  rect 1x0.75 smd: 1(-2.795,1.905) 2(-2.795,0.635) 3(-2.795,-0.635) 4(-2.795,-1.905)
  rect 4.055x4.56 smd: 5(0.698,0)
  Top Layer region: 0,-2.775 0,2.775 -0.905,2.775 -0.905,-2.775
  Top Layer region: 3.2,1.53 3.2,2.28 2.655,2.28 2.655,1.53
  Top Layer region: 3.2,-2.28 3.2,-1.53 2.65,-1.53 2.65,-2.28
  silkscreen extent -3.1,-2.6 3.1,2.9, body extent -3.17,-2.67 3.17,2.67, height 1.11
SOD-323F [mm] "NXP recommended land pattern"
  rect 0.6x0.6 smd paste-0.05: 1(-1.1,0) 2(1.1,0)
  silkscreen extent -2.06,-0.86 1.53,0.86, body extent -1.35,-0.67 1.35,0.68, height 0.79
Testpoint_Keystone_Miniature [mil] "Miniature SMT test point"
  rect 135x70 smd: 1(0,0)
  silkscreen extent -78,-46 78,45, body extent -52,-20 52,20, height 61
TI_Stacked_Overlay_Small [mil]
  silkscreen extent -418,-98 418,98
TSW-112-07-G-S [mm] "Samtec 100mil, 1x12, 230 mil above insulator"
  rrect6% 1.65x1.65 hole 1.016 mask+0: 1(-13.97,0)
  round 1.65 hole 1.016 mask+0: 2(-11.43,0) 3(-8.89,0) 4(-6.35,0) 5(-3.81,0) 6(-1.27,0) 7(1.27,0) 8(3.81,0) 9(6.35,0) 10(8.89,0) 11(11.43,0) 12(13.97,0)
  silkscreen extent -15.24,-1.27 15.24,1.65, body extent -15.24,-1.27 15.24,1.27, height 8.38
WE-HC6 [mm] "Wurth Electronik recommended land pattern"
  rect 3.85x4 smd: 1(-3.825,0) 2(3.825,0)
  silkscreen extent -6.2,-6.2 6.2,6.2, body extent -5.76,-5.36 5.74,5.34, height 5
WEEE_Minimum [mil] "WEEElie bin"
  silkscreen extent -95,-172 99,104

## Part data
C1: library part CMP-0011173-2, "CAP, AL, 47 uF, 50 V, +/- 20%, 0.3 ohm, SMD", Cap_Case=G, Manufacturer=Panasonic, Supplier Part Number 1=PCE4020CT-ND, Tolerance_%=20%, Value1="0.3 ohm", Value2=50V, ValueDisplayed=47uF
C2 C3: library part CMP-0007722-2, "CAP, CERM, 0.1 uF, 100 V, +/- 10%, X7R, 0805", Cap_Case=0805, Manufacturer=Kemet, Supplier Part Number 1=399-3486-1-ND, TempCo=X7R, Tolerance_%=10%, Value1="0.064 ohm", Value2=100V, ValueDisplayed=0.1uF
C4 C5 C6 C7 C8 C14 C15 C16 C23 C24 C25: library part CMP-0082268-1, "CAP, CERM, 4.7 µF, 100 V,+/- 10%, X7S, AEC-Q200 Grade 1, 1210", Cap_Case=1210, Manufacturer=MuRata, Supplier Part Number 1=490-14484-1-ND, TempCo=X7S, Tolerance_%=10%, Value1="0.001 ohm", Value2=100V, ValueDisplayed=4.7µF
C9: library part CMP-0008374-2, "CAP, CERM, 0.47 uF, 100 V, +/- 10%, X7R, 0805", Cap_Case=0805, Manufacturer=MuRata, Supplier Part Number 1=490-3326-1-ND, TempCo=X7R, Tolerance_%=10%, Value1=Unknown, Value2=100V, ValueDisplayed=0.47uF
C10: library part CMP-0007138-4, "CAP, CERM, 0.47 uF, 16 V, +/- 10%, X7R, AEC-Q200 Grade 1, 0603", Cap_Case=0603, Manufacturer=MuRata, Supplier Part Number 1=490-4775-1-ND, TempCo=X7R, Tolerance_%=10%, Value1=Unknown, Value2=16V, ValueDisplayed=0.47uF
C11 C12 C13: library part CMP-0007370-4, "CAP, CERM, 2.2 uF, 10 V, +/- 10%, X7R, 0603", Cap_Case=0603, Manufacturer=MuRata, Supplier Part Number 1=490-4520-1-ND, TempCo=X7R, Tolerance_%=10%, Value1="0.009 ohm", Value2=10V, ValueDisplayed=2.2uF
C17 C18 C19 C20 C21 C22: library part CMP-0006333-2, "CAP, CERM, 0.01 uF, 100 V, +/- 10%, X7S, AEC-Q200 Grade 1, 0402", Cap_Case=0402, Manufacturer=TDK, Supplier Part Number 1=445-6910-1-ND, TempCo=X7S, Tolerance_%=10%, Value1="0.410191 ohm", Value2=100V, ValueDisplayed=0.01uF
C26 C27 C28 C34 C39 C44: library part CMP-0007077-5, "CAP, CERM, 0.1 uF, 25 V, +/- 10%, X7R, AEC-Q200 Grade 1, 0603", Cap_Case=0603, Manufacturer=TDK, Supplier Part Number 1=445-5667-1-ND, TempCo=X7R, Tolerance_%=10%, Value1=Unknown, Value2=25V, ValueDisplayed=0.1uF
C29 C30 C31 C32 C35 C36 C37 C38: library part CMP-0093793-1, "Chip Multilayer Ceramic Capacitors for General Purpose, 1210, 100uF, X7U, +22%/-56%, 20%, 6.3V", Manufacturer=Murata, Operating Temperature Range="-55°C to +125°C", TempCo=+22%/-56%, Temperature Characteristic=X7U, Tolerance_%=20%, ValueDisplayed=100uF
C33: library part CMP-0007469-4, "CAP, CERM, 0.1 uF, 100 V, +/- 10%, X7R, 0603", Cap_Case=0603, Manufacturer=MuRata, Supplier Part Number 1=490-3285-1-ND, TempCo=X7R, Tolerance_%=10%, Value1=Unknown, Value2=100V, ValueDisplayed=0.1uF
C40 C41: library part CMP-0006722-4, "CAP, CERM, 33 pF, 100 V, +/- 5%, C0G/NP0, 0603", Cap_Case=0603, Manufacturer=AVX, Supplier Part Number 1=478-1143-1-ND, TempCo=C0G/NP0, Tolerance_%=5%, Value1="0.209 ohm", Value2=100V, ValueDisplayed=33pF
C42: library part CMP-0012661-3, "CAP, Tantalum Polymer, 220 uF, 10 V, +/- 20%, 0.025 ohm, AEC-Q200 Grade 1, 7343-31 SMD", Cap_Case=7.3x4.3x3.1mm, Manufacturer=Kemet, Supplier Part Number 1=399-12102-1-ND, Tolerance_%=20%, Value1="0.025 ohm", Value2=10V, ValueDisplayed=220uF
C43: library part CMP-0006768-4, "CAP, CERM, 150 pF, 50 V, +/- 5%, C0G/NP0, 0603", Cap_Case=0603, Manufacturer=AVX, Supplier Part Number 1=478-1177-1-ND, TempCo=C0G/NP0, Tolerance_%=5%, Value1="0.098 ohm", Value2=50V, ValueDisplayed=150pF
C45: library part CMP-0080102-1, "CAP, CERM, 0.22 µF, 16 V,+/- 10%, X7R, AEC-Q200 Grade 1, 0603", Cap_Case=0603, Manufacturer=Samsung, Supplier Part Number 1=1276-6868-1-ND, TempCo=X7R, Tolerance_%=10%, Value2=16V, ValueDisplayed=0.22µF
C46: library part CMP-0007468-5, "CAP, CERM, 0.01 uF, 100 V, +/- 10%, X7R, 0603", Cap_Case=0603, Manufacturer=MuRata, Supplier Part Number 1=GRM188R72A103KA01D-ND, TempCo=X7R, Tolerance_%=10%, Value1=Unknown, Value2=100V, ValueDisplayed=0.01uF
C47: library part CMP-0078296-1, "CAP, CERM, 6800 pF, 50 V,+/- 5%, C0G/NP0, 0603", Cap_Case=0603, Manufacturer=MuRata, Supplier Part Number 1=490-11477-1-ND, TempCo=C0G/NP0, Tolerance_%=5%, Value2=50V, ValueDisplayed=6800pF
C48 C49: library part CMP-0006735-1, "CAP, CERM, 220 pF, 100 V, +/- 10%, X7R, 0603", Cap_Case=0603, Manufacturer=AVX, Supplier Part Number 1=478-1195-1-ND, TempCo=X7R, Tolerance_%=10%, Value1="0.579 ohm", Value2=100V, ValueDisplayed=220pF
D1 D2: library part CMP-0077011-2, "Diode, Schottky, 60 V, 1 A, SOD-323F", Manufacturer=Nexperia, PartNumber=PMEG6010CEJ,115, Value1=1A, Value2=0.66V
FID1 FID2 FID3 FID4 FID5 FID6: library part CMP-0077181-1, "Fiducial mark.  There is nothing to buy or mount.", Manufacturer=N/A
H1 H2 H3 H4: library part CMP-0003617-1, "Machine Screw, Round, #4-40 x 1/4, Nylon, Philips panhead", Manufacturer="B&F Fastener Supply", Supplier Part Number 1=H542-ND
H5 H6 H7 H8: library part CMP-0003610-1, "Standoff, Hex, 0.5\"L #4-40 Nylon", Manufacturer=Keystone, Supplier Part Number 1=36-1902C-ND
J1: library part CMP-0055161-1, "TEST POINT SLOTTED .118\", TH", Manufacturer=Keystone, Supplier Part Number 1=36-1040-ND
J2: library part CMP-0055554-1, "Receptacle, 9.52mm, 2x1, TH", Color=Green, Current_A=32A, Manufacturer="Phoenix Contact", Supplier Part Number 1=277-1271-ND, Voltage_V=1kV
J3: library part CMP-0077513-2, "Terminal Block, 10.16mm, 2x1, Tin, R/A, TH", Color=Green, Current_A=65A, Manufacturer=Eaton, Supplier Part Number 1=283-4339-ND, Voltage_V=300V
J4: library part CMP-0075424-1, "Header, 100mil, 12x1, Gold, TH", Color=Black, Current_A=6.3A, Manufacturer=Samtec, Supplier Part Number 1=SAM1029-12-ND, Voltage_V=550V
L1: library part CMP-0063966-1, "Inductor, Shielded Drum Core, Superflux, 4.2 uH, 11 A, 0.0068 ohm, SMD", Manufacturer="Wurth Elektronik", Supplier Part Number 1=732-1170-1-ND, Value1="0.0068 ohm", Value2=11A, ValueDisplayed=4.2uH
L2 L3: library part CMP-0094401-1, "Inductor 1.5uH 1.6mOhm 32.5A", Manufacturer=Cyntec, Operating Temperature Range="to +180°C"
Logo1: library part CMP-0074844-1
Logo2: library part CMP-0074837-2, "IEC 61010-1 Hot Surface Warning", Manufacturer="Texas Instruments"
Logo3: library part CMP-0074838-1, "Texas Instrument Corporate Signature"
Logo4: library part CMP-0074847-1, "FCC_disclaimer"
Logo5: library part CMP-0074769-1
NT1: library part CMP-0078142-4, "Single point connection between nets.", Manufacturer=N/A
Q1 Q2: library part CMP-0092446-1, "N-Channel 11A (Ta), 42A (Tc) 3.6W (Ta), 54W (Tc) Surface Mount 5-DFN (5x6) (8-SOFL)", Digikey Part Number=488-NVMFS6H852NLWFT1GTR-ND, Drain To Source Breakdown Voltage=80V, Input Capacitace At Vds="906pF @ 40V", Manufacturer="ON Semiconductor", Mouser Part Number=863-NVMFS6H852NLWFTG, Operating Temperature Range="-55°C to +175°C", Power_W=3.6W, Pulse Drain Current=208A, Typ Forward Diode Voltage=0.81V
Q3 Q4: library part CMP-0750157-1, "MOSFET, N-CH, 80 V, 157 A, AEC-Q101, SO-8FL", Alternate Manufacturer=None, Manufacturer="ON Semiconductor", Value1="? ohm", Value2="64 nC"
R1: library part CMP-0022900-4, "RES, 1.00, 1%, 0.1 W, 0603", Manufacturer=Yageo, Power_W=100mW, Supplier Part Number 1=311-1.00HRCT-ND, TempCo="200 ppm/C", Tolerance_%=1%, Value2=0.1W, Value_Code=1R00, ValueDisplayed=1.00
R2: library part CMP-0018617-3, "RES, 1.0, 5%, 0.25 W, AEC-Q200 Grade 0, 1206", Manufacturer=Vishay-Dale, Power_W=250mW, Supplier Part Number 1=541-1.0ECT-ND, TempCo="200 ppm/C", Tolerance_%=5%, Value2=0.25W, Value_Code=1R00, ValueDisplayed=1.0
R3 R4 R7 R8 R9 R10 R15 R17 R18 R19 R20: library part CMP-0021990-4, "RES, 100 k, 1%, 0.1 W, AEC-Q200 Grade 0, 0603", Manufacturer=Vishay-Dale, Power_W=100mW, Supplier Part Number 1=541-100KHCT-ND, TempCo="100 ppm/C", Tolerance_%=1%, Value2=0.1W, Value_Code=100k
R5 R6: library part CMP-0023154-5, "RES, 4.87 k, 1%, 0.1 W, 0603", Manufacturer=Yageo, Power_W=100mW, Supplier Part Number 1=311-4.87KHRCT-ND, TempCo="100 ppm/C", Tolerance_%=1%, Value2=0.1W, Value_Code=4k87, ValueDisplayed=4.87k
R11 R14 R16: library part CMP-0025697-4, "RES, 0, 5%, 0.1 W, AEC-Q200 Grade 0, 0603", Manufacturer=Vishay-Dale, Power_W=100mW, Supplier Part Number 1=541-0.0GCT-ND, TempCo="200 ppm/C", Tolerance_%=5%, Value2=0.1W, Value_Code=0000, ValueDisplayed=0
R12 R13: library part CMP-0021991-4, "RES, 100, 1%, 0.1 W, AEC-Q200 Grade 0, 0603", Manufacturer=Vishay-Dale, Power_W=100mW, Supplier Part Number 1=541-100HCT-ND, TempCo="100 ppm/C", Tolerance_%=1%, Value2=0.1W, Value_Code=100R, ValueDisplayed=100
R21: library part CMP-0023155-5, "RES, 4.99 k, 1%, 0.1 W, 0603", Manufacturer=Yageo, Power_W=100mW, Supplier Part Number 1=311-4.99KHRCT-ND, TempCo="100 ppm/C", Tolerance_%=1%, Value2=0.1W, Value_Code=4k99, ValueDisplayed=4.99k
R22: library part CMP-0022220-4, "RES, 22.1 k, 1%, 0.1 W, AEC-Q200 Grade 0, 0603", Manufacturer=Vishay-Dale, Power_W=100mW, Supplier Part Number 1=541-22.1KHCT-ND, TempCo="100 ppm/C", Tolerance_%=1%, Value2=0.1W, Value_Code=22k1, ValueDisplayed=22.1k
R23: library part CMP-0023263-5, "RES, 73.2 k, 1%, 0.1 W, 0603", Manufacturer=Yageo, Power_W=100mW, Supplier Part Number 1=311-73.2KHRCT-ND, TempCo="100 ppm/C", Tolerance_%=1%, Value2=0.1W, Value_Code=73k2, ValueDisplayed=73.2k
R24 R25 R26 R27: library part CMP-0026992-3, "RES, 0, 5%, 0.1 W, AEC-Q200 Grade 0, 0402", Manufacturer=Panasonic, Power_W=100mW, Supplier Part Number 1=P0.0JCT-ND, TempCo="600 ppm/C", Tolerance_%=5%, Value2=0.1W, Value_Code=0000, ValueDisplayed=0
R28 R29: library part CMP-0020693-3, "RES, 2.2, 5%, 0.125 W, AEC-Q200 Grade 0, 0805", Manufacturer=Panasonic, Power_W=125mW, Supplier Part Number 1=P2.2ACT-ND, TempCo="600 ppm/C", Tolerance_%=5%, Value2=0.125W, Value_Code=2R20, ValueDisplayed=2.2
SH-J1: library part CMP-0078738-1, "Single Operation 2.54mm Pitch Open Top Jumper Socket", Manufacturer=Harwin, Supplier Part Number 1=952-2881-ND
TP1 TP2 TP3 TP4: library part CMP-0055152-1, "Test Point, Miniature, SMT", Manufacturer=Keystone, Supplier Part Number 1=36-5015TR-ND
U1: library part CMP-0079128-2, "3.5-V to 65-V Low IQ, Dual Synchronous Buck DC-DC Controller, RWG0040A (VQFNP-40)", Alternate Manufacturer="Texas Instruments", Alternate PartNumber=LM5143QRWGTQ1, Operating Temperature Range="-40 to 125 C", Rating=Automotive
ZZ1: library part CMP-0077236-1
ZZ2: library part CMP-0077237-1
ZZ3: library part CMP-0077238-1
ZZ4: library part CMP-0077238-1, "Place Shunt Jumper SH-J1 onto J2 pins VDDA - DEMB"

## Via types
v1: diameter 22, hole 10, Top Layer to Bottom Layer, tented both sides, 504 vias
v2: diameter 22, hole 8, Top Layer to Bottom Layer, tented both sides, 24 vias
v3: diameter 19.68, hole 7.87, Top Layer to Bottom Layer, 5 vias
v4: diameter 24, hole 8, Top Layer to Bottom Layer, tented both sides, 2 vias

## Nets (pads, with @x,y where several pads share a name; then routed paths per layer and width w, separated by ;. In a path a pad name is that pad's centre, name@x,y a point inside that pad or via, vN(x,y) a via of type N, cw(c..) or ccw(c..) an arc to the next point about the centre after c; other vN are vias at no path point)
AGND: C10.1 C43.2 C44.2 C45.2 C46.2 C47.2 J4.8 NT1.1 R22.1 R23.1 U1.3 U1.35 | length 521.3
  Top Layer w9: NT1.1@1499.84,2530 U1.35@1499.84,2544.17 1499.84,2569.84
  Top Layer w9.5: 1276.38,2483.62 1324.79,2483.62 1329.2,2479.21 U1.3@1375.83,2479.21
  Top Layer w16: 1499.84,2569.84 1500,2570 1500,2710
  Top Layer w24: 1660,2800 J4.8@1660,3040
COMP: C43.1 R21.2 U1.2 U1.29 | length 1155.8
  Top Layer w9: v1@1310,2530 1309.07,2530.93 v1(1305,2530.93) 1305,2530 1336.1,2498.9 U1.2@1375.83,2498.9 ; U1.29@1604.17,2498.9 1648.9,2498.9 1662.44,2512.44 v1(1662.44,2527.44) 1685,2550 1707.44,2550 R21.2@1710,2547.44 1714.75,2552.19 C43.1@1761.33,2552.19
  Bottom Layer w9: v1(1305,2530.93) 1303.4,2532.53 1289.95,2532.53 1256.7,2565.78 1256.7,2696.2 1310.16,2749.67 1611.14,2749.99 ; 1611.14,2749.69 1650.32,2749.69 1710,2690 1710,2575 v1(1662.44,2527.44)
DEMB: J4.7 U1.33 | length 503.6
  Top Layer w9: U1.33@1539.21,2544.17 1539.21,2594.21 1560,2615
  Signal Layer 4 w9: J4.7@1560,3040 1560,2970 1570,2960 v1(1570,2620)
EN1: J4.10 R20.1 U1.31 | length 836.4
  Top Layer w9: U1.31@1578.58,2544.17 1578.58,2568.58 1590,2580 v1(1600,2580)
  Signal Layer 2 w9: v1(1600,2580) 1860,2840 J4.10@1860,3045
  Bottom Layer w9: J4.10@1860,3045 1860,3095 1910,3145 R20.1@2002.44,3145
EN2: J4.2 R19.1 U1.40 | length 731.4
  Top Layer w9: v1(1325,2615) 1370,2570 1390,2570 1401.42,2558.58 U1.40@1401.42,2544.17
  Signal Layer 2 w9: J4.2@1060,3045 1060,2880 v1(1325,2615)
  Bottom Layer w9: J4.2@1060,3045 R19.1@1060,3122.44
FB1: R15.1 R16.1 R22.2 U1.28 | length 264.3
  Top Layer w9.5: U1.28@1604.17,2479.21 1700.79,2479.21 v1(1705,2483.43) 1716.57,2495 R22.2@1752.44,2495 R15.1@1752.44,2440
  Bottom Layer w9.5: v1(1705,2483.43) 1726.18,2483.43 1728.9,2486.14 R16.1@1758.35,2486.14
NetC1_2: C1.2 R2.2 | length 181.4
  Top Layer w34: C1.2@3262.25,978.74 3265.44,975.55 3265.44,803.19 R2.2@3268.63,800
NetC2_2: C2.2 C3.1 C4.1 C5.1 J2.1 L1.1 TP1.1
NetC11_1: C11.1 R1.1 U1.6 | length 275.9
  Top Layer w9: C11.1@1157.56,2351.98 1157.56,2399.84 R1.1@1159.86,2402.14 ; R1.1@1157.56,2404.43 1215.79,2404.43 1231.51,2420.16 U1.6@1375.83,2420.16
NetC26_1: C26.1 C48.1 L2.2 Q1.1 Q1.2 Q1.3 Q3.5 R3.2 R5.2 U1.21 | length 1075.5
  Top Layer w9.5: U1.21@1604.17,2341.42 1618.58,2341.42 1636.87,2323.13 1636.87,2298.17 C26.1@1645.22,2289.83 ; C26.1@1650.36,2295.37 C26.1@1660.04,2285.69
  Top Layer w16: C26.1@1645.22,2294.83 1645.22,2290.81 1653.95,2282.08 1683.97,2282.08 1688.17,2277.87 v1(1689.8,2277.87) ; L2.2@2160.55,1582 L2.2@2160.55,1666.7
  Signal Layer 2 w20: v1@1690.72,2278.25 1690.72,2277.49 1695.62,2277.49 2007.8,1965.31 2075.53,1965.31 2199.78,1841.05 v4@2199.78,1828.96
  Bottom Layer w12: R3.2@2201.33,1796.7 v4@2201.33,1827.41
  Bottom Layer w16: v1(2160.8,1568.76) 2160.8,1528.94 R5.2@2161.05,1528.7 ; v4@2200.92,1828.94 v4(2199.8,1828.94) v4@2201.33,1827.41 ; R3.2@2201.33,1796.7 2209.08,1788.95 R3.2@2210,1788.95
  Bottom Layer w20: v4@2200.92,1828.94 2213.93,1841.94 C48.1@2252.93,1841.94
NetC26_2: C26.2 D1.1 U1.20 | length 170.9
  Top Layer w9.5: U1.20@1578.58,2315.83 1578.58,2305.13 1626.35,2257.36 1626.35,2255.38 1635.52,2246.21 C26.2@1648.68,2246.21 ; D1.1@1645.22,2170.48 1645.62,2170.89 1645.62,2234.3 C26.2@1645.22,2234.71
NetC27_1: C27.1 C49.1 L3.1 Q2.1 Q2.2 Q2.3 Q4.5 R4.1 R6.2 U1.10 | length 1056.2
  Top Layer w9.5: C27.1@1320,2292.52 1320.69,2292.52 C27.1@1331.69,2303.51 ; C27.1@1331.69,2296.14 1332.27,2296.14 1343.26,2307.14 1343.26,2326.04 1358.64,2341.42 U1.10@1375.83,2341.42
  Top Layer w16: L3.1@851.99,1592.65 L3.1@851.99,1674.5 ; v1(1271.69,2282.05) 1273.31,2282.05 1287.4,2296.14 C27.1@1322.95,2296.14
  Signal Layer 2 w20: v4(803.01,1895.83) 803.01,1945.36 814.77,1957.13 967.04,1957.13 1272.78,2262.86 1272.78,2280.42 1272.07,2281.13 1272.07,2281.51 v1@1272.61,2282.05
  Bottom Layer w16: R4.1@796.79,1934.73 R4.1@801.97,1939.92 802.49,1939.4 802.49,1896.34 v4(803.01,1895.83) ; R6.2@851.99,1528.3 v1(851.99,1582)
  Bottom Layer w20: C49.1@753.64,1891.95 756.75,1895.06 802.24,1895.06 v4(803.01,1895.83)
NetC27_2: C27.2 D2.1 U1.11 | length 179.8
  Top Layer w9.5: D2.1@1326.25,2176.36 1327.71,2177.82 1327.71,2237.04 C27.2@1331.69,2241.02 ; C27.2@1327.71,2241.65 1341.65,2241.65 1401.42,2301.42 U1.11@1401.42,2315.83
NetC28_1: C28.1 R5.1 R7.1 R12.2 | length 1179.1
  Top Layer w10: R12.2@1832.44,2366.1 1832.8,2365.74 v1(1832.8,2324.88)
  Signal Layer 4 w10: v1(1832.8,2324.88) 1835.1,2322.59 1835.1,2308.45 1842.13,2301.42 1842.13,2232.6 1951.01,2123.71 1951.01,1643.89 2115.96,1478.94 v1@2115.96,1460.26
  Bottom Layer w10: R7.1@2107.69,1409.22 2158.74,1409.22 C28.1@2160.55,1411.03 2161.05,1411.53 2161.05,1465.7 2124.66,1465.7 2119.21,1460.26 v1@2115.96,1460.26
  other v1: 2115.82,1462.67
NetC34_1: C34.1 R6.1 R8.2 R13.2 | length 1310.4
  Top Layer w10: v1(1060,2457.56) R13.2@1104.11,2457.56
  Signal Layer 4 w10: v1(903.7,1462.36) 903.7,1515.59 1105.93,1717.82 1105.93,2244.07 1060,2290 v1(1060,2457.56)
  Bottom Layer w10: v1(903.7,1462.36) 854.94,1462.36 851.99,1465.31 851.99,1417.92 861.68,1408.23 R8.2@915.95,1408.23
NetC40_1: C40.1 R11.1 U1.26 | length 412.2
  Top Layer w9: U1.26@1604.17,2439.84 1636.79,2439.84 1640.32,2443.37 1659.68,2443.37 1676.43,2426.63 1708.37,2426.63 v1(1710,2425) ; v1(1861.65,2520.59) R11.1@1861.65,2491 1863.01,2489.65 C40.1@1915.04,2489.65
  Bottom Layer w9: v1(1710,2425) 1804.51,2425 1861.65,2482.14 v1(1861.65,2520.59)
NetC40_2: C40.2 R12.1 U1.27 | length 497.5
  Top Layer w9: U1.27@1604.17,2459.53 1632.61,2459.53 1633.33,2460.25 1666.67,2460.25 1667.39,2459.53 1675.47,2459.53 1685,2450 v1(1690,2450) ; R12.1@1887.56,2366.1 1907.24,2366.1 1915.04,2373.9 C40.2@1915.04,2434.53 1944.7,2434.53 v1(1955.25,2434.91) v1@1951.73,2434.91
  Signal Layer 2 w9: v1(1690,2450) 1941.13,2450 1955.25,2435.89 v1(1955.25,2434.91)
NetC41_1: C41.1 R14.1 U1.5 | length 428.2
  Top Layer w8: R14.1@1021.61,2513.7 1024.41,2510.9 v1(1063.76,2510.9) C41.1@1103.11,2510.9 ; v1(1201.03,2435) 1202.66,2436.63 1242.14,2436.63 1245.36,2439.84 U1.5@1375.83,2439.84
  Bottom Layer w8: v1(1063.76,2510.9) 1139.66,2435 v1(1201.03,2435)
NetC41_2: C41.2 R13.1 U1.4 | length 266.7
  Top Layer w9: C41.2@1157.75,2511.37 C41.2@1158.23,2510.9 1158.23,2463.44 1161.67,2460 1353.06,2460 ; 1353.53,2459.53 U1.4@1375.83,2459.53
NetC45_1: C45.1 U1.32 | length 125.3
  Top Layer w9: U1.32@1558.9,2544.17 1558.9,2575.84 1600,2616.94 C45.1@1600,2652.44
NetC46_1: C46.1 U1.38 | length 182.3
  Top Layer w9: C46.1@1340,2652.44 1350,2640 1350,2620 1363.51,2606.49 1419.65,2606.49 1440.79,2585.35 U1.38@1440.79,2544.17
NetC47_1: C47.1 R21.1 | length 52.5
  Top Layer w9: R21.1@1710,2602.56 1758.58,2602.56 C47.1@1761.33,2605.32
NetC48_2: C48.2 R28.2 | length 108.7
  Bottom Layer w16: R28.2@2145.66,1894.6 R28.2@2149,1897.94
  Bottom Layer w20: R28.2@2149,1897.94 C48.2@2252.93,1897.94
NetC49_2: C49.2 R29.2 | length 72.6
  Bottom Layer w20: C49.2@753.64,1835.95 817.79,1835.95 R29.2@823.74,1830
